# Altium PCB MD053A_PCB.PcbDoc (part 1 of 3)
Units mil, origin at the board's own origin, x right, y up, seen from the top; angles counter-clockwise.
Board outline 3650 x 5180 mil, 4 copper layers (Top Layer, GND Layer, Power Layer, Bottom Layer), stack 58.4 mil thick; 251 components, 138 nets, 532 pads, 1017 vias.
Unrouted connection lines stored in the file: 42.
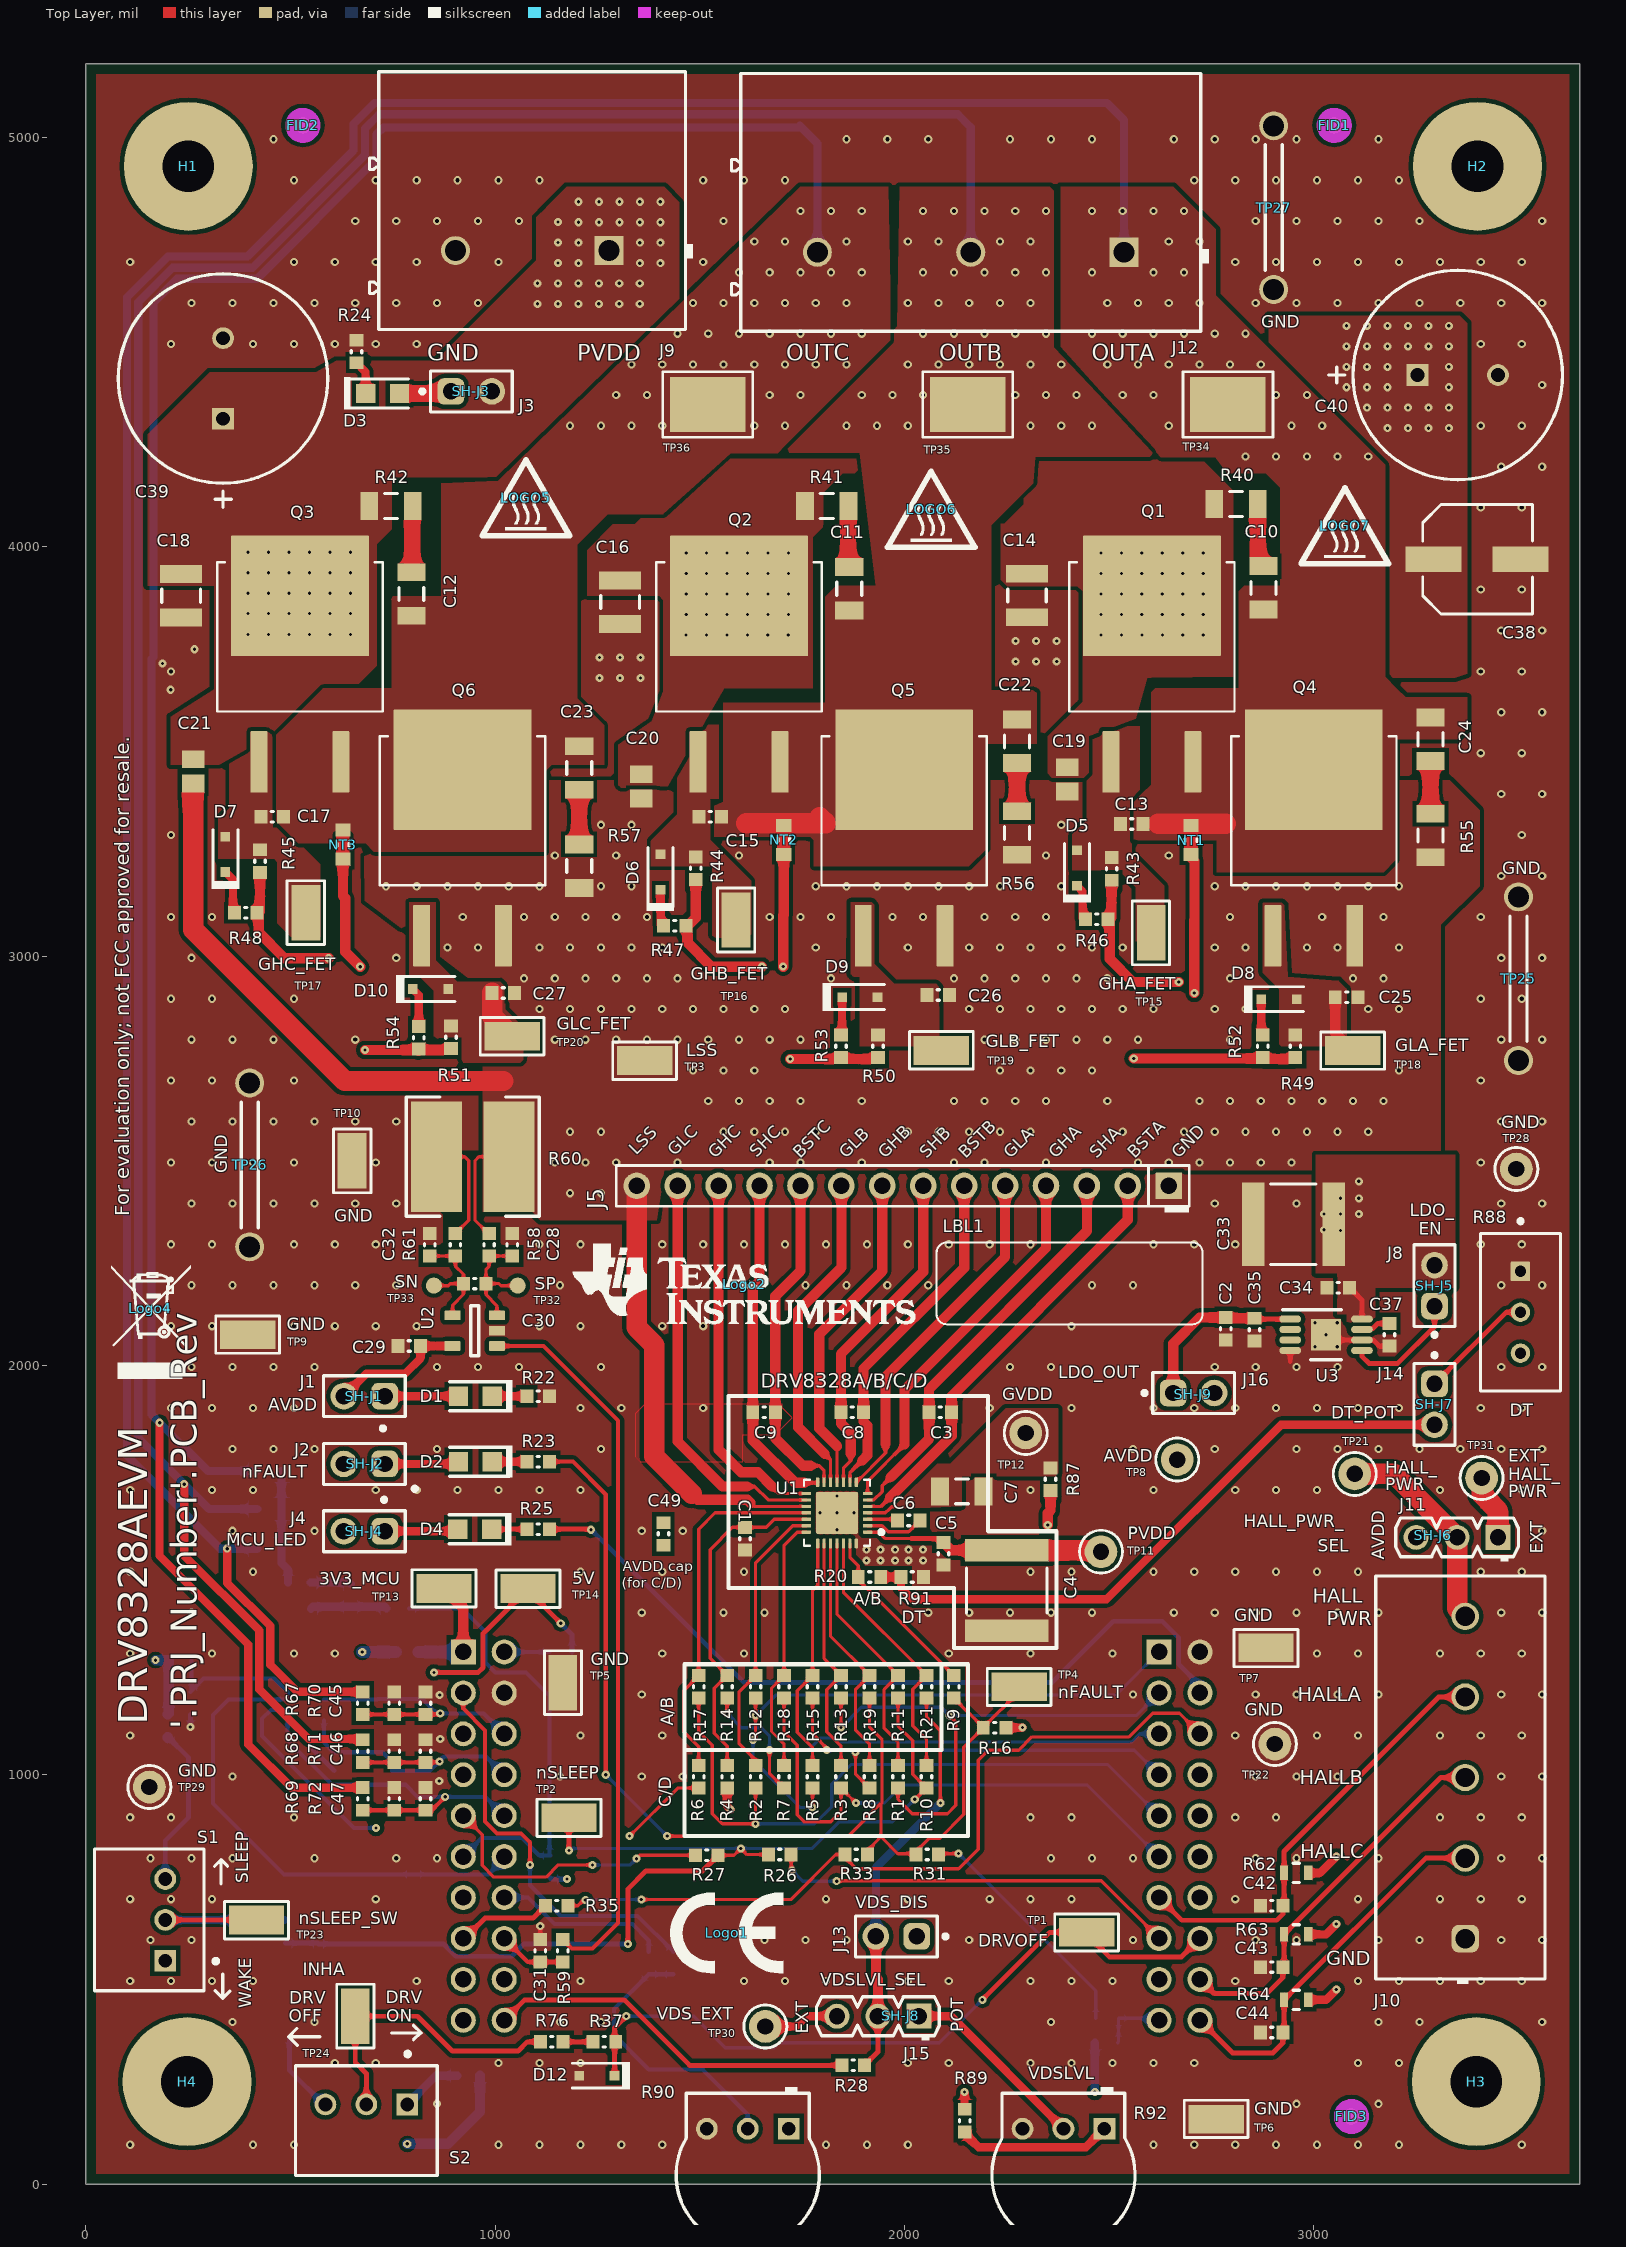
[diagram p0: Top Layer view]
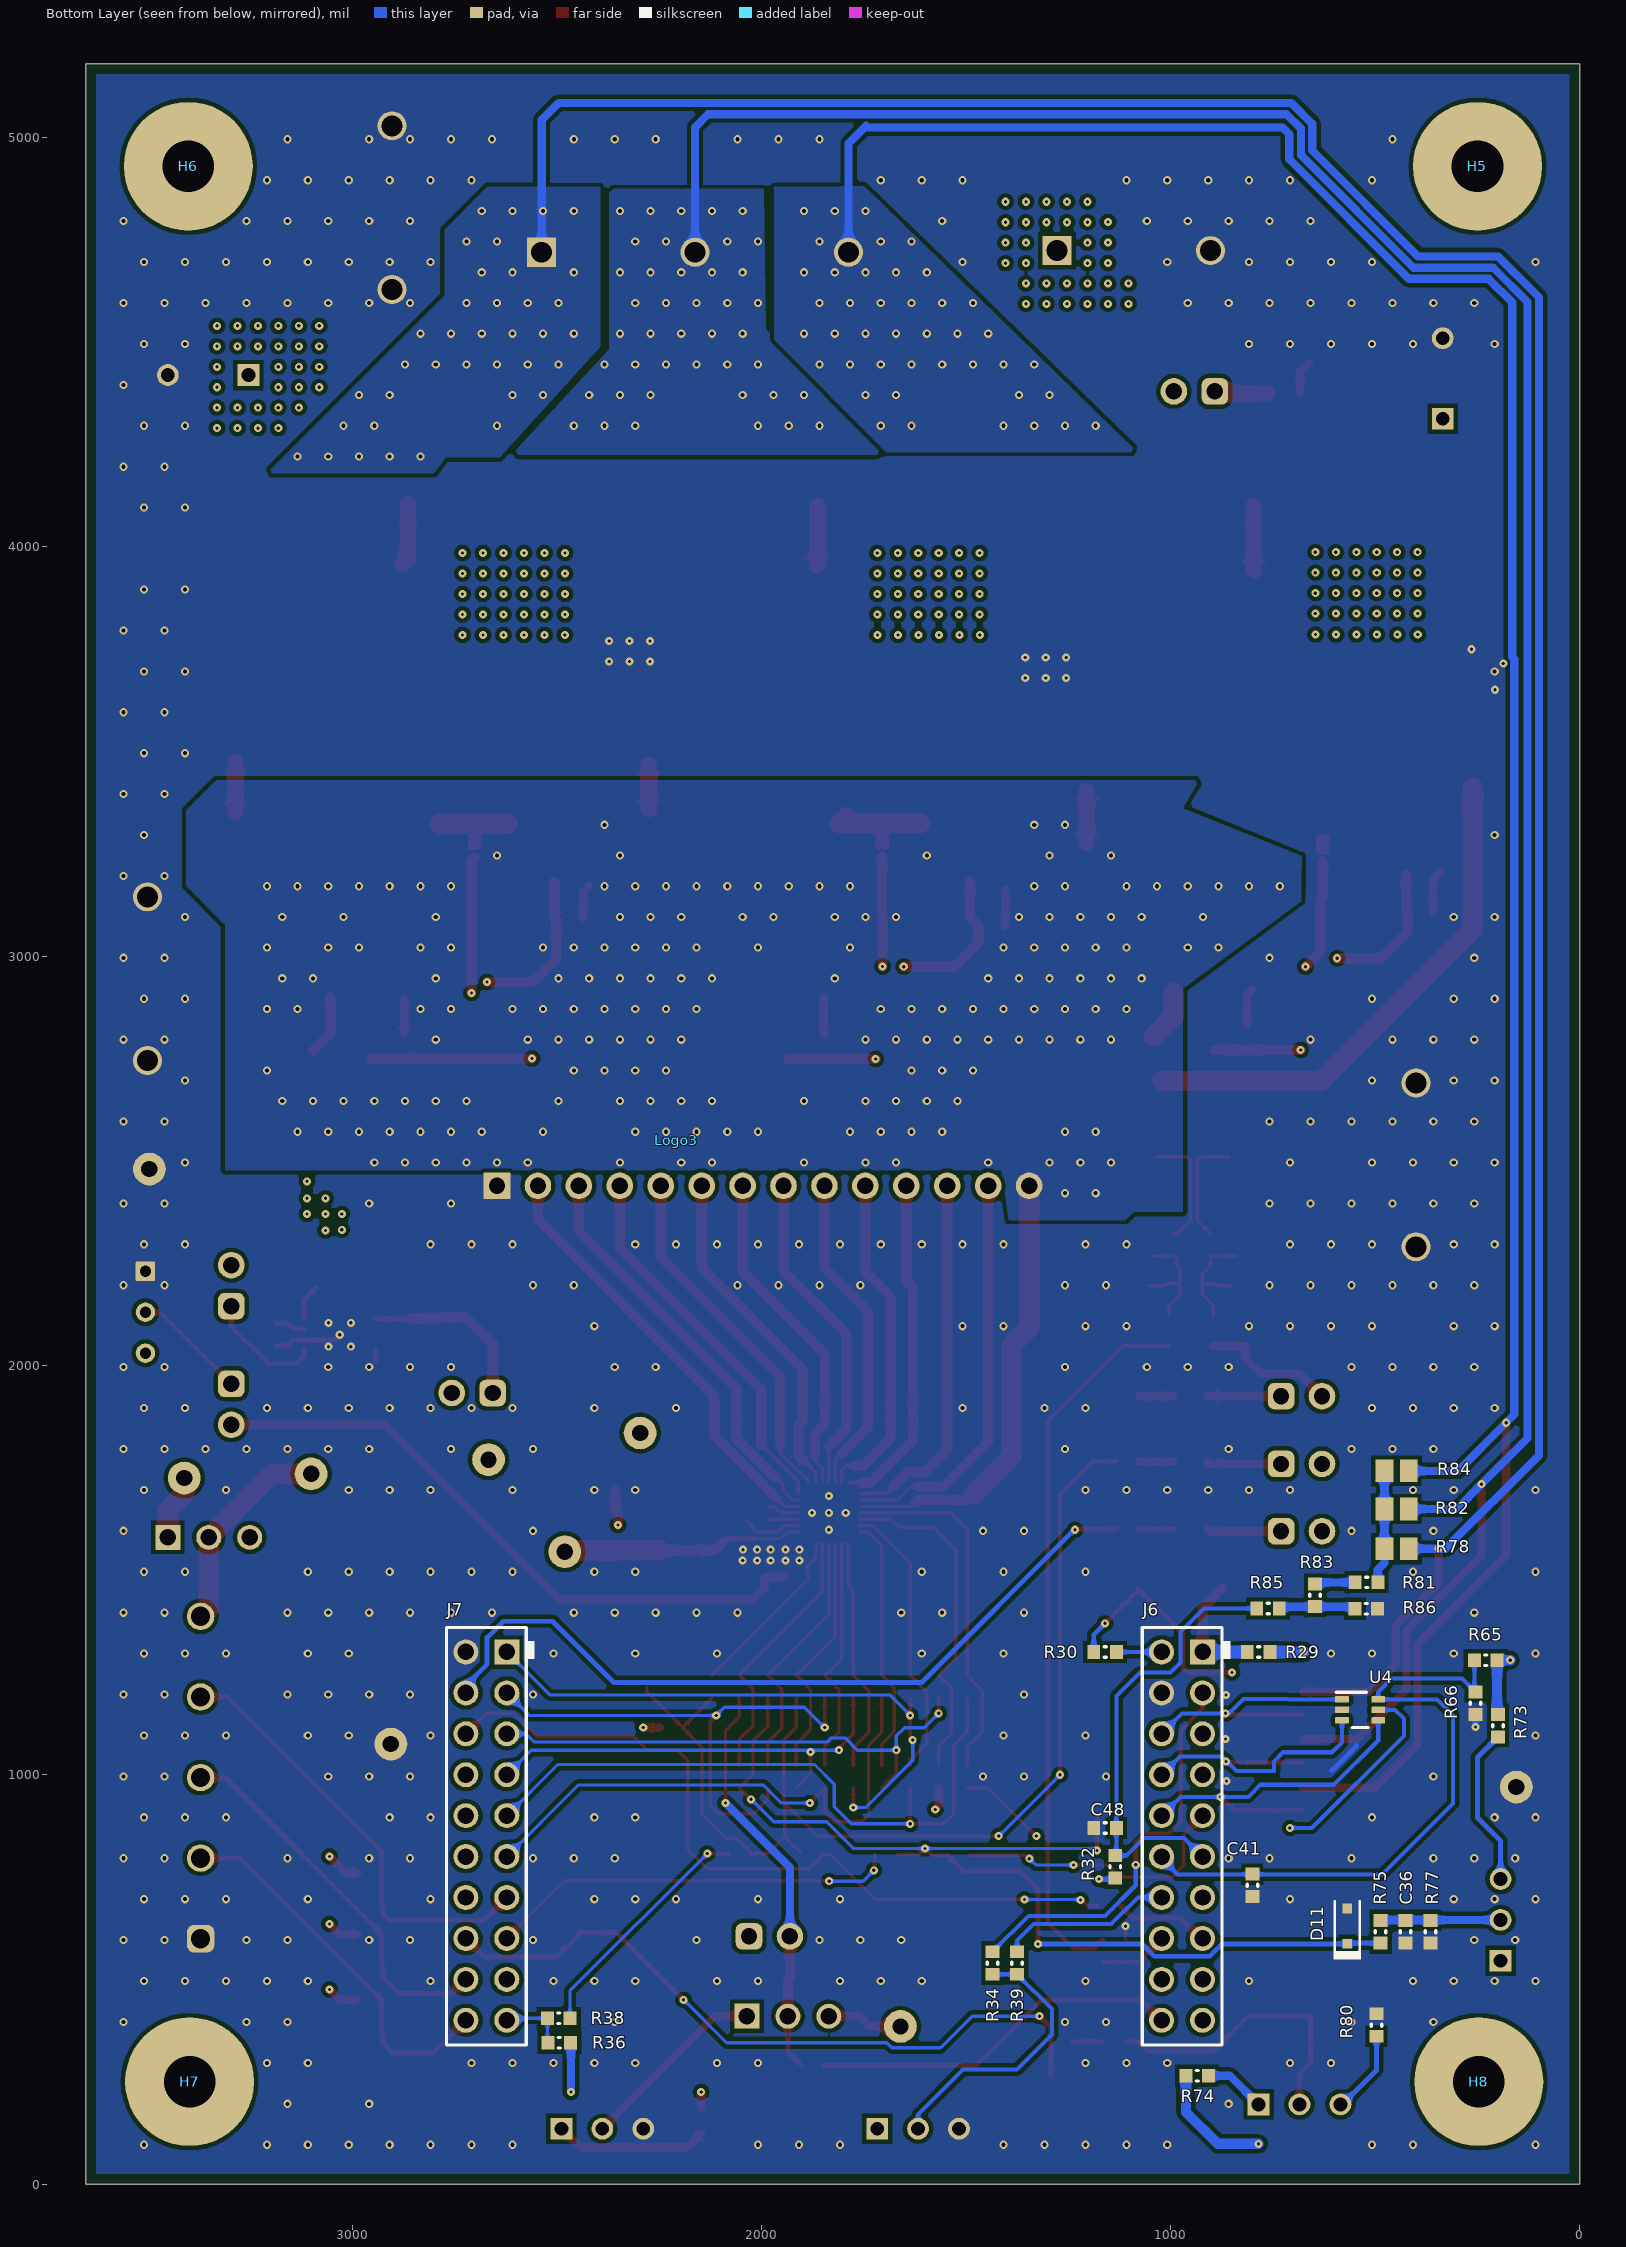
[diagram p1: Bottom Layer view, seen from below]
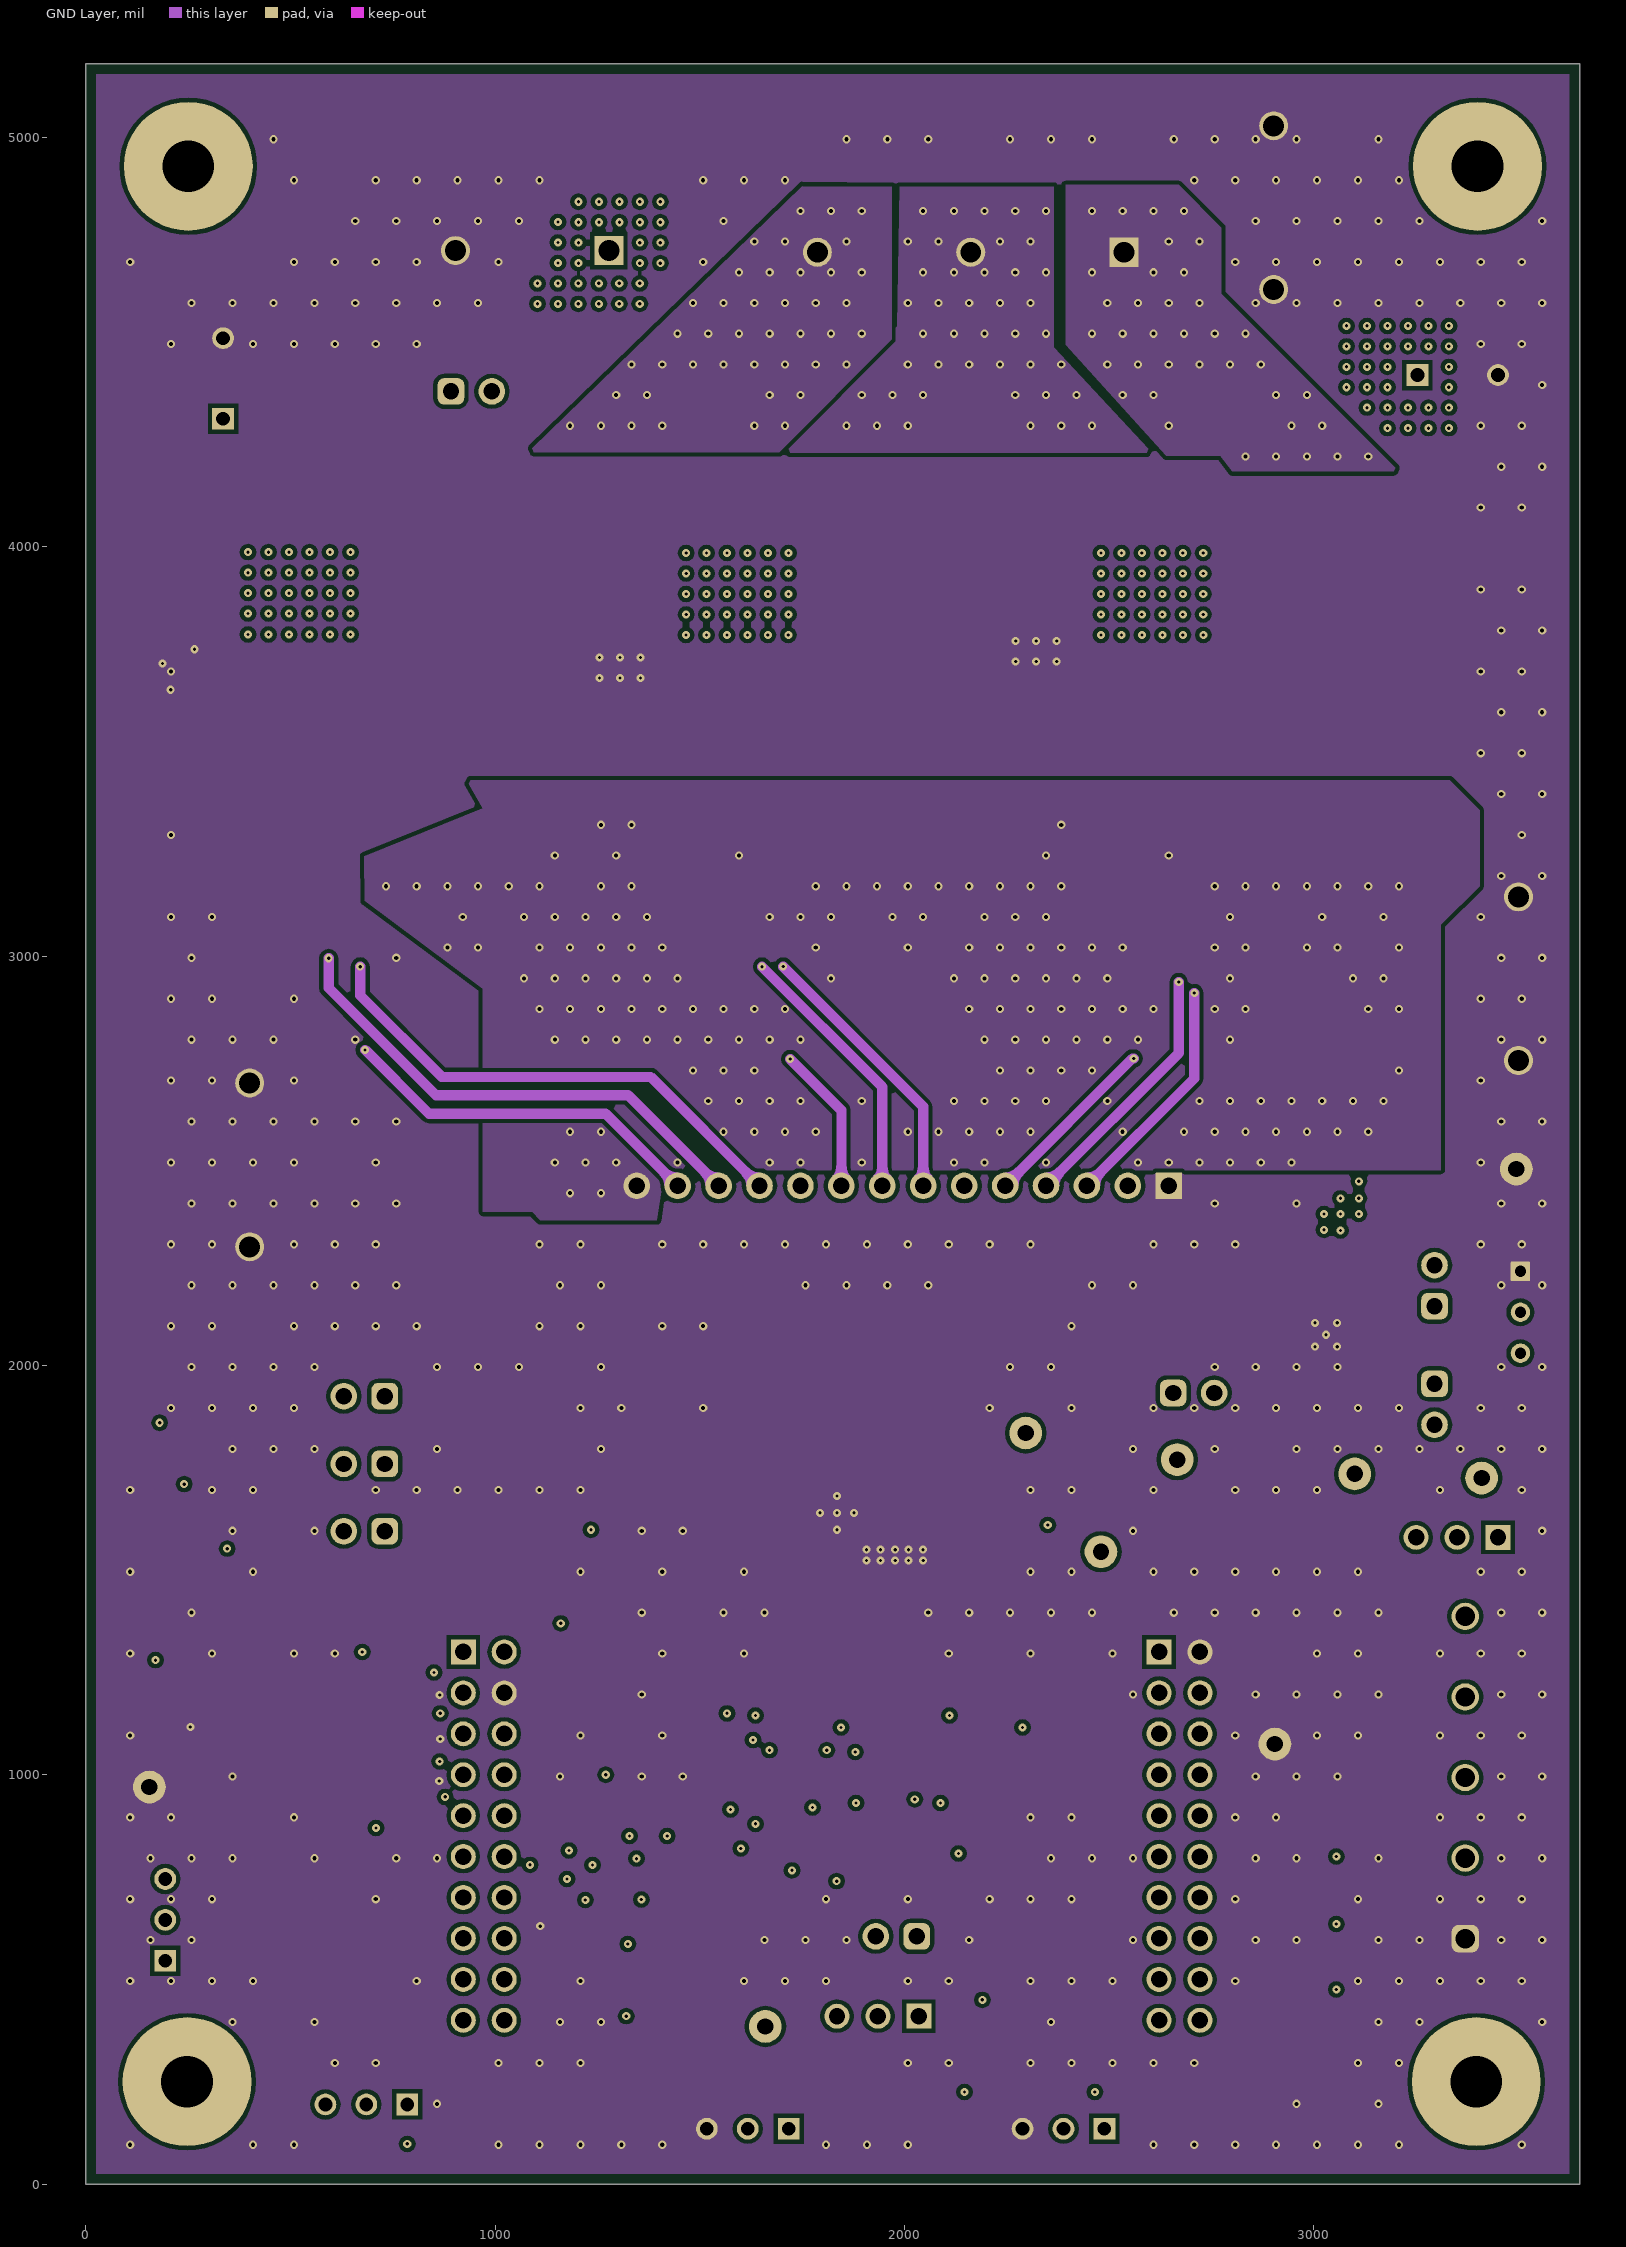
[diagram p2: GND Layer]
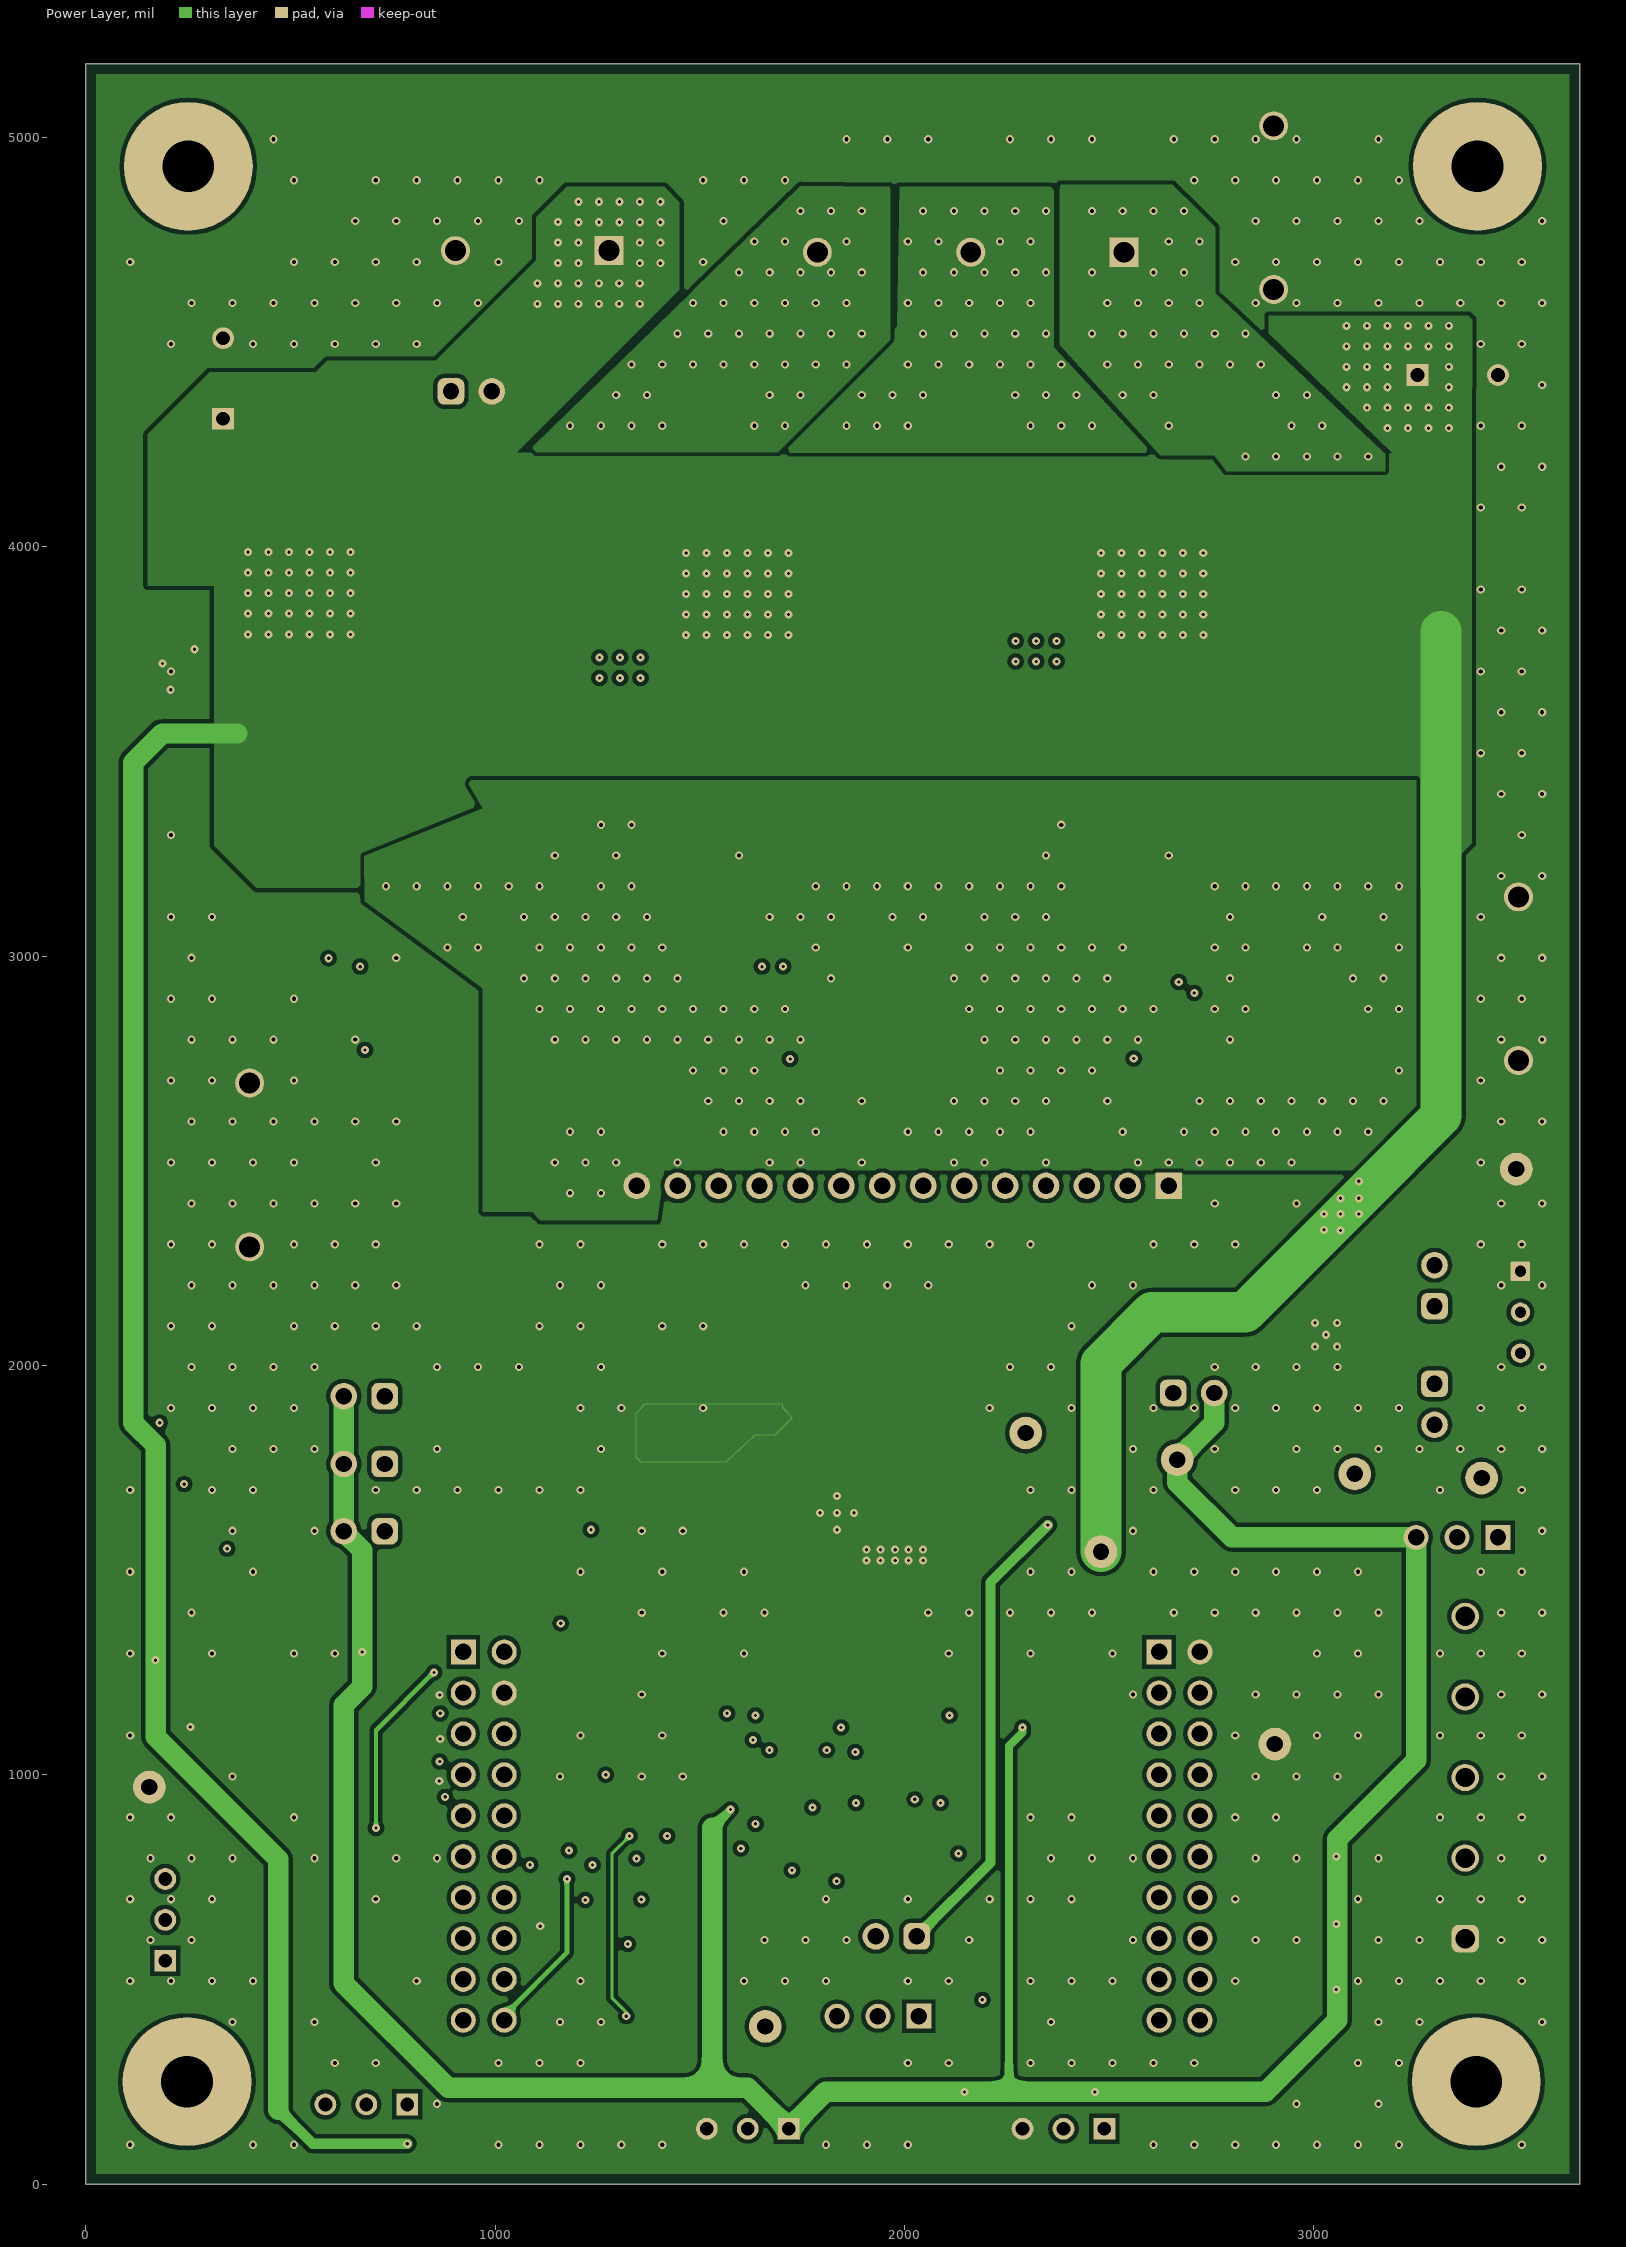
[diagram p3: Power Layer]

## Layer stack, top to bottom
Top Solder: solder mask 0.4, Solder Resist, Dk 3.5
Top Layer: signal copper 2.8
Dielectric 2: core 10, FR-4, Dk 4.8
GND Layer: signal copper 1.4
Dielectric 1: prepreg 30, FR-4, Dk 4.2
Power Layer: signal copper 1.4
Dielectric 3: core 10, FR-4, Dk 4.8
Bottom Layer: signal copper 2.8
Solder Side: solder mask 0.4, Solder Resist, Dk 3.5

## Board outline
0,0 3650,0 3650,5180 0,5180

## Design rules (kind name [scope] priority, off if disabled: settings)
AcuteAngle [All] p1: minimum=4.50000000000000E+0001 checktracksonly=FALSE
AssemblyTestPointUsage [All] p1: valid=2
BoardOutlineClearance BoardOutlineClearance_MountingHoles [OnCopper and InComponentClass('Mounting Holes')] p1: gap=39.37 ignorepadtopadclearanceinfootprint=FALSE
BoardOutlineClearance BoardOutlineClearance_Poly [OnCopper and IsPoly] p2: gap=25 ignorepadtopadclearanceinfootprint=FALSE
BoardOutlineClearance [OnCopper and Not InComponentClass('Logo') and not InComponentClass('FiducialMark') and not InRegion(1000,500,4000,800) and not InPoly] p3: gap=75 ignorepadtopadclearanceinfootprint=FALSE
Clearance Clearance_Keepouts [((IsTrack Or IsArc) And Not InPoly) And IsFree and IsKeepOut vs ((IsTrack Or IsArc) And Not InPoly) And IsFree and IsKeepOut] p1: gap=0 ignorepadtopadclearanceinfootprint=FALSE
Clearance Clearance_Poly [InPolygon] p2: gap=10 ignorepadtopadclearanceinfootprint=TRUE
Clearance Clearance_FiducialMark [IsKeepOut and InComponentClass('FiducialMark') vs IsPad and InComponentClass('FiducialMark')] p3: gap=0 ignorepadtopadclearanceinfootprint=FALSE
Clearance [All] p4: gap=7 ignorepadtopadclearanceinfootprint=TRUE
ComponentClearance ComponentClearance_MountingHoles_FiducialMarks [InComponentClass('Mounting Holes') vs InComponentClass('FiducialMark')] p1: gap=50 collisioncheckmode=3 verticalgap=10 showdistances=FALSE
ComponentClearance ComponentClearance_Shunt [InComponentClass('Header') vs InComponentClass('Shunt')] p2: gap=0 collisioncheckmode=3 verticalgap=0 showdistances=FALSE
ComponentClearance ComponentClearance_Logo [InComponentClass('Logo')] p3: gap=50 collisioncheckmode=3 verticalgap=10 showdistances=FALSE
ComponentClearance ComponentClearance_ScrewToNut [(HasFootprint('NY PMS 440 0025 PH')) vs (HasFootprint('Keystone_1902C'))] p4: gap=5 collisioncheckmode=3 verticalgap=10 showdistances=FALSE
ComponentClearance ComponentClearance_MountingHoles [InComponentClass('Mounting Holes')] p5: gap=10 collisioncheckmode=3 verticalgap=100000 showdistances=FALSE
ComponentClearance ComponentClearance_SmallPassives [HasFootprint('0201*') or HasFootprint('0402*') or HasFootprint('0508') or HasFootprint('0603*') or HasFootprint('0612') or HasFootprint('0805*') or HasFootprint('0815*') or HasFootprint('0830*') or HasFootprint('1206*') or HasFootprint('1210*') or HasFootprint('1808*') or HasFootprint('1812*') or HasFootprint('1825*') or HasFootprint('2010*') or HasFootprint('2220*') or HasFootprint('2225*') or HasFootprint('2512*') or HasFootprint('2728*') or HasFootprint('3518*') vs HasFootprint('0201*') or HasFootprint('0402*') or HasFootprint('0508') or HasFootprint('0603*') or HasFootprint('0612') or HasFootprint('0805*') or HasFootprint('0815*') or HasFootprint('0830*') or HasFootprint('1206*') or HasFootprint('1210*') or HasFootprint('1808*') or HasFootprint('1812*') or HasFootprint('1825*') or HasFootprint('2010*') or HasFootprint('2220*') or HasFootprint('2225*') or HasFootprint('2512*') or HasFootprint('2728*') or HasFootprint('3518*')] p6: gap=14.96 collisioncheckmode=3 verticalgap=10 showdistances=FALSE
ComponentClearance ComponentClearance_THtoSMT [IsThruComponent vs IsSMTComponent] p7: gap=40 collisioncheckmode=3 verticalgap=30 showdistances=FALSE
ComponentClearance ComponentClearance_THtoTH [IsThruComponent vs IsThruComponent] p8: gap=30 collisioncheckmode=3 verticalgap=30 showdistances=FALSE
ComponentClearance [All] p9: gap=30 collisioncheckmode=3 verticalgap=10 showdistances=FALSE
DiffPairsRouting [All] p1: maxlimit=100 minlimit=10 mostfreqgap=10 toplayer_minwidth=15 toplayer_maxwidth=15 toplayer_prefwidth=15 midlayer1_minwidth=15 midlayer1_maxwidth=15 midlayer1_prefwidth=15 midlayer2_minwidth=15 midlayer2_maxwidth=15 midlayer2_prefwidth=15 bottomlayer_minwidth=15 bottomlayer_maxwidth=15 bottomlayer_prefwidth=15 maxuncoupledlength=1000
FabricationTestPointUsage TestPointUsage [All] p1: valid=2 allowmultiple=FALSE
FabricationTestpoint Testpoint [All] p1: side=3 testpointundercomponent=TRUE minsize=40 maxsize=100 preferedsize=60 minholesize=0 maxholesize=40 preferedholesize=32 testpointgrid=1 allowsidetop=TRUE allowsidebottom=TRUE usegrid=TRUE gridtolerance=0.01
FanoutControl Fanout_LCC [IsLCC] p1: bgadir=Out bgaviamode=Centered fanoutstyle=Auto fanoutdirection=Alternating viagrid=1 // Fanout_LCC (Default Rule)
FanoutControl Fanout_BGA [IsBGA] p2: bgadir=Out bgaviamode=Centered fanoutstyle=Auto fanoutdirection=Alternating viagrid=1 // Fanout_BGA (Default Rule)
FanoutControl Fanout_Default [All] p4: bgadir=Out bgaviamode=Centered fanoutstyle=Auto fanoutdirection=Alternating viagrid=1 // Fanout_Default (Default Rule)
FanoutControl Fanout_Small [(CompPinCount < 5)] p5: bgadir=Out bgaviamode=Centered fanoutstyle=Auto fanoutdirection=OutThenIn viagrid=1 // Fanout_Small (Default Rule)
Height [All] p1 off: minheight=0 maxheight=1000 prefheight=500
HoleSize [All] p1: absolutevalues=TRUE maxlimit=251 minlimit=7.87 maxpercent=80.000 minpercent=20.000
MinimumAnnularRing MinimumAnnularRing_ThermalPadVias [IsVia and InAnyComponent] p1: minimumring=5.91
MinimumAnnularRing [All] p2: minimumring=5
MinimumSolderMaskSliver MinimumSolderMaskSliver_Logo [InComponentClass('Logo') vs InComponentClass('Logo')] p1: minsoldermaskwidth=0.7
MinimumSolderMaskSliver [All] p2: minsoldermaskwidth=1
PlaneConnect [All] p1: planeconnectstyle=Direct reliefexpansion=10 reliefentries=4 reliefconductorwidth=10 reliefairgap=10
PolygonConnect PolygonConnect_51 [All] p1: connectstyle=Direct reliefconductorwidth=10 reliefentries=4 polygonreliefangle="90 Angle" airgapwidth=10
PolygonConnect PolygonConnect_50 [All vs IsNamedPolygon('TOP_LAYER_PVDD_P078')] p2: connectstyle=Direct reliefconductorwidth=10 reliefentries=4 polygonreliefangle="90 Angle" airgapwidth=10
PolygonConnect PolygonConnect_49 [All vs IsNamedPolygon('TOP_LAYER_PVDD_P078')] p3: connectstyle=Direct reliefconductorwidth=10 reliefentries=4 polygonreliefangle="90 Angle" airgapwidth=10
PolygonConnect PolygonConnect_48 [All vs IsNamedPolygon('TOP_LAYER_PVDD_P078')] p4: connectstyle=Direct reliefconductorwidth=10 reliefentries=4 polygonreliefangle="90 Angle" airgapwidth=10
PolygonConnect PolygonConnect_47 [All vs IsNamedPolygon('TOP_LAYER_PVDD_P008')] p5: thpad.connectstyle=Direct thpad.reliefconductorwidth=10 thpad.reliefentries=4 thpad.polygonreliefangle="90 Angle" thpad.airgapwidth=10 smdpad.connectstyle=Direct smdpad.reliefconductorwidth=10 smdpad.reliefentries=4 smdpad.polygonreliefangle="90 Angle" smdpad.airgapwidth=10 via.connectstyle=Relief via.reliefconductorwidth=10 via.reliefentries=4 via.polygonreliefangle="90 Angle" via.airgapwidth=10
PolygonConnect PolygonConnect_46 [All vs IsNamedPolygon('BOTTOM_LAYER_GND_P080')] p6: connectstyle=Direct reliefconductorwidth=10 reliefentries=4 polygonreliefangle="90 Angle" airgapwidth=10
PolygonConnect PolygonConnect_45 [All vs IsNamedPolygon('BOTTOM_LAYER_OUTA_P076')] p7: connectstyle=Direct reliefconductorwidth=10 reliefentries=4 polygonreliefangle="90 Angle" airgapwidth=10
PolygonConnect PolygonConnect_44 [All vs IsNamedPolygon('BOTTOM_LAYER_OUTB_P074')] p8: connectstyle=Direct reliefconductorwidth=10 reliefentries=4 polygonreliefangle="90 Angle" airgapwidth=10
PolygonConnect PolygonConnect_43 [All vs IsNamedPolygon('BOTTOM_LAYER_OUTC_P072')] p9: connectstyle=Direct reliefconductorwidth=10 reliefentries=4 polygonreliefangle="90 Angle" airgapwidth=10
PolygonConnect PolygonConnect_42 [All vs IsNamedPolygon('BOTTOM_LAYER_NONET_P070')] p10: connectstyle=Direct reliefconductorwidth=10 reliefentries=4 polygonreliefangle="90 Angle" airgapwidth=10
PolygonConnect PolygonConnect_41 [All vs IsNamedPolygon('POWER_LAYER_GND_P078')] p11: connectstyle=Direct reliefconductorwidth=10 reliefentries=4 polygonreliefangle="90 Angle" airgapwidth=10
PolygonConnect PolygonConnect_40 [All vs IsNamedPolygon('GND_LAYER_GND_P074')] p12: connectstyle=Direct reliefconductorwidth=10 reliefentries=4 polygonreliefangle="90 Angle" airgapwidth=10
PolygonConnect PolygonConnect_39 [All vs IsNamedPolygon('TOP_LAYER_GND_P070')] p13: connectstyle=Direct reliefconductorwidth=10 reliefentries=4 polygonreliefangle="90 Angle" airgapwidth=10
PolygonConnect PolygonConnect_38 [All vs IsNamedPolygon('BOTTOM_LAYER_GND')] p14: connectstyle=Direct reliefconductorwidth=10 reliefentries=4 polygonreliefangle="90 Angle" airgapwidth=10
PolygonConnect PolygonConnect_37 [All vs IsNamedPolygon('BOTTOM_LAYER_GND')] p15: connectstyle=Direct reliefconductorwidth=10 reliefentries=4 polygonreliefangle="90 Angle" airgapwidth=10
PolygonConnect PolygonConnect_36 [All vs IsNamedPolygon('GND_LAYER_OUTA_P062')] p16: connectstyle=Direct reliefconductorwidth=10 reliefentries=4 polygonreliefangle="90 Angle" airgapwidth=10
PolygonConnect PolygonConnect_35 [All vs IsNamedPolygon('GND_LAYER_OUTB_P060')] p17: connectstyle=Direct reliefconductorwidth=10 reliefentries=4 polygonreliefangle="90 Angle" airgapwidth=10
PolygonConnect PolygonConnect_34 [All vs IsNamedPolygon('GND_LAYER_OUTC_P058')] p18: connectstyle=Direct reliefconductorwidth=10 reliefentries=4 polygonreliefangle="90 Angle" airgapwidth=10
PolygonConnect PolygonConnect_33 [All vs IsNamedPolygon('POWER_LAYER_PVDD_P056')] p19: connectstyle=Direct reliefconductorwidth=10 reliefentries=4 polygonreliefangle="90 Angle" airgapwidth=10
PolygonConnect PolygonConnect_32 [All vs IsNamedPolygon('POWER_LAYER_PVDD_P056')] p20: connectstyle=Direct reliefconductorwidth=10 reliefentries=4 polygonreliefangle="90 Angle" airgapwidth=10
PolygonConnect PolygonConnect_31 [All vs IsNamedPolygon('POWER_LAYER_OUTA_P052')] p21: connectstyle=Direct reliefconductorwidth=10 reliefentries=4 polygonreliefangle="90 Angle" airgapwidth=10
PolygonConnect PolygonConnect_30 [All vs IsNamedPolygon('POWER_LAYER_OUTB_P050')] p22: connectstyle=Direct reliefconductorwidth=10 reliefentries=4 polygonreliefangle="90 Angle" airgapwidth=10
PolygonConnect PolygonConnect_29 [All vs IsNamedPolygon('POWER_LAYER_OUTC_P048')] p23: connectstyle=Direct reliefconductorwidth=10 reliefentries=4 polygonreliefangle="90 Angle" airgapwidth=10
PolygonConnect PolygonConnect_28 [All vs IsNamedPolygon('POWER_LAYER_AVDD_P064')] p24: connectstyle=Direct reliefconductorwidth=10 reliefentries=4 polygonreliefangle="90 Angle" airgapwidth=10
PolygonConnect PolygonConnect_27 [All vs IsNamedPolygon('SIGNAL_LAYER_1_OUTA_P060')] p25: connectstyle=Direct reliefconductorwidth=10 reliefentries=4 polygonreliefangle="90 Angle" airgapwidth=10
PolygonConnect PolygonConnect_26 [All vs IsNamedPolygon('SIGNAL_LAYER_1_OUTB_P058')] p26: connectstyle=Direct reliefconductorwidth=10 reliefentries=4 polygonreliefangle="90 Angle" airgapwidth=10
PolygonConnect PolygonConnect_25 [All vs IsNamedPolygon('SIGNAL_LAYER_1_OUTC_P056')] p27: connectstyle=Direct reliefconductorwidth=10 reliefentries=4 polygonreliefangle="90 Angle" airgapwidth=10
PolygonConnect PolygonConnect_24 [All vs IsNamedPolygon('SIGNAL_LAYER_2_PVDD_P054')] p28: connectstyle=Direct reliefconductorwidth=10 reliefentries=4 polygonreliefangle="90 Angle" airgapwidth=10
PolygonConnect PolygonConnect_23 [All vs IsNamedPolygon('SIGNAL_LAYER_2_PVDD_P052')] p29: connectstyle=Direct reliefconductorwidth=10 reliefentries=4 polygonreliefangle="90 Angle" airgapwidth=10
PolygonConnect PolygonConnect_22 [All vs IsNamedPolygon('SIGNAL_LAYER_2_OUTA_P050')] p30: connectstyle=Direct reliefconductorwidth=10 reliefentries=4 polygonreliefangle="90 Angle" airgapwidth=10
PolygonConnect PolygonConnect_21 [All vs IsNamedPolygon('SIGNAL_LAYER_2_OUTB_P048')] p31: connectstyle=Direct reliefconductorwidth=10 reliefentries=4 polygonreliefangle="90 Angle" airgapwidth=10
PolygonConnect PolygonConnect_20 [All vs IsNamedPolygon('SIGNAL_LAYER_2_OUTC_P046')] p32: connectstyle=Direct reliefconductorwidth=10 reliefentries=4 polygonreliefangle="90 Angle" airgapwidth=10
PolygonConnect PolygonConnect_19 [All vs IsNamedPolygon('TOP_LAYER_AVDD_P046')] p33: connectstyle=Direct reliefconductorwidth=10 reliefentries=4 polygonreliefangle="90 Angle" airgapwidth=10
PolygonConnect PolygonConnect_18 [All vs IsNamedPolygon('TOP_LAYER_PVDD_P034')] p34: connectstyle=Direct reliefconductorwidth=10 reliefentries=4 polygonreliefangle="90 Angle" airgapwidth=10
PolygonConnect PolygonConnect_17 [All vs IsNamedPolygon('SIGNAL_LAYER_1_OUTC_P036')] p35: connectstyle=Direct reliefconductorwidth=10 reliefentries=4 polygonreliefangle="90 Angle" airgapwidth=10
PolygonConnect PolygonConnect_16 [All vs IsNamedPolygon('TOP_LAYER_PVDD_P034')] p36: connectstyle=Direct reliefconductorwidth=10 reliefentries=4 polygonreliefangle="90 Angle" airgapwidth=10
PolygonConnect PolygonConnect_15 [All vs IsNamedPolygon('TOP_LAYER_LSS_P030')] p37: connectstyle=Direct reliefconductorwidth=10 reliefentries=4 polygonreliefangle="90 Angle" airgapwidth=10
PolygonConnect PolygonConnect_14 [All vs IsNamedPolygon('TOP_LAYER_GLC_FET_P024')] p38: connectstyle=Direct reliefconductorwidth=10 reliefentries=4 polygonreliefangle="90 Angle" airgapwidth=10
PolygonConnect PolygonConnect_13 [All vs IsNamedPolygon('TOP_LAYER_GLB_FET_P026')] p39: connectstyle=Direct reliefconductorwidth=10 reliefentries=4 polygonreliefangle="90 Angle" airgapwidth=10
PolygonConnect PolygonConnect_12 [All vs IsNamedPolygon('TOP_LAYER_GLA_FET_P028')] p40: connectstyle=Direct reliefconductorwidth=10 reliefentries=4 polygonreliefangle="90 Angle" airgapwidth=10
PolygonConnect PolygonConnect_11 [All vs IsNamedPolygon('TOP_LAYER_GHB_FET_P020')] p41: connectstyle=Direct reliefconductorwidth=10 reliefentries=4 polygonreliefangle="90 Angle" airgapwidth=10
PolygonConnect PolygonConnect_10 [All vs IsNamedPolygon('TOP_LAYER_GHA_FET_P022')] p42: connectstyle=Direct reliefconductorwidth=10 reliefentries=4 polygonreliefangle="90 Angle" airgapwidth=10
PolygonConnect PolygonConnect_9 [All vs IsNamedPolygon('TOP_LAYER_GHC_FET_P018')] p43: connectstyle=Direct reliefconductorwidth=10 reliefentries=4 polygonreliefangle="90 Angle" airgapwidth=10
PolygonConnect PolygonConnect_8 [All vs IsNamedPolygon('TOP_LAYER_GND_P014')] p44: connectstyle=Direct reliefconductorwidth=10 reliefentries=4 polygonreliefangle="90 Angle" airgapwidth=10
PolygonConnect PolygonConnect_7 [All vs IsNamedPolygon('TOP_LAYER_GND_P014')] p45: connectstyle=Direct reliefconductorwidth=10 reliefentries=4 polygonreliefangle="90 Angle" airgapwidth=10
PolygonConnect PolygonConnect_6 [All vs IsNamedPolygon('TOP_LAYER_PVDD_P008')] p46: connectstyle=Direct reliefconductorwidth=10 reliefentries=4 polygonreliefangle="90 Angle" airgapwidth=10
PolygonConnect PolygonConnect_5 [All vs IsNamedPolygon('TOP_LAYER_PVDD_P008')] p47: connectstyle=Direct reliefconductorwidth=10 reliefentries=4 polygonreliefangle="90 Angle" airgapwidth=10
PolygonConnect PolygonConnect_4 [All vs IsNamedPolygon('TOP_LAYER_PVDD_P008')] p48: connectstyle=Direct reliefconductorwidth=10 reliefentries=4 polygonreliefangle="90 Angle" airgapwidth=10
PolygonConnect PolygonConnect_3 [All vs IsNamedPolygon('TOP_LAYER_OUTA_P006')] p49: connectstyle=Direct reliefconductorwidth=10 reliefentries=4 polygonreliefangle="90 Angle" airgapwidth=10
PolygonConnect PolygonConnect_2 [All vs IsNamedPolygon('TOP_LAYER_OUTB_P004')] p50: connectstyle=Direct reliefconductorwidth=10 reliefentries=4 polygonreliefangle="90 Angle" airgapwidth=10
PolygonConnect PolygonConnect_1 [All vs IsNamedPolygon('TOP_LAYER_OUTC_P002')] p51: connectstyle=Direct reliefconductorwidth=10 reliefentries=4 polygonreliefangle="90 Angle" airgapwidth=10
PolygonConnect [All] p52: connectstyle=Relief reliefconductorwidth=10 reliefentries=4 polygonreliefangle="90 Angle" airgapwidth=10
RoutingVias ThermalPadVias [IsVia and InAnyComponent] p1: holewidth=7.87 width=19.68 viastyle="Through Hole" minholewidth=7.87 minwidth=19.68 maxholewidth=12.99 maxwidth=23.62
RoutingVias [All] p2: holewidth=7.87 width=19.68 viastyle="Through Hole" minholewidth=7.87 minwidth=19.68 maxholewidth=10 maxwidth=20
SilkToBoardRegionClearance [Not ((IsComment or IsDesignator) And (Hide <> 'False')) and not InRegion(1000,500,4000,800)] p1:
SilkToSilkClearance SilkToSilkClearance_Pb-FreeLogo [(HasFootprint('Pb-Free_Overlay_Medium') OR HasFootprint('Pb-Free_Overlay_Small')) vs (HasFootprint('Pb-Free_Overlay_Medium') OR HasFootprint('Pb-Free_Overlay_Small'))] p1: silktosilkclearance=0
SilkToSilkClearance [All] p2: silktosilkclearance=0
SilkToSolderMaskClearance SilkToComponentPadClearance [(IsPad or IsFill or IsRegion) and InAnycomponent] p1: minsilkscreentomaskgap=0 clearancetoexposedcopper=TRUE
SilkToSolderMaskClearance "Silk to Solder Mask Opening" [All] p2: minsilkscreentomaskgap=0 clearancetoexposedcopper=FALSE
SolderMaskExpansion [All] p1: expansion=1.97
UnRoutedNet [All] p1: checkbadconnections=TRUE
Width [All] p1: maxlimit=100 minlimit=6 preferedwidth=10 checkconnectedcopper=TRUE
13 further rules are at their usual default settings.

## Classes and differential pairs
component class MD053A_LDO: C2 C33 C34 C35 C37 J8 J16 SH-J5 SH-J9 U3
component class Label: LBL1
component class Shunt: SH-J1 SH-J2 SH-J3 SH-J4 SH-J5 SH-J6 SH-J7 SH-J8 SH-J9
component class MD053A_POWER_AND_CONNECTORS: C36 C38 C39 C40 C41 C42 C43 C44 C45 C46 C47 C48 D11 D12 GND1 GND2 GND3 J9 J10 J11 J12 J13 J14 J15 R37 R62 R63 R64 R65 R66 R67 R68 R69 R70 R71 R72 R73 R74 R75 R76 R77 R78 R80 R81 R82 R83 R84 R85 R86 R87 R88 R89 R90 R91 R92 S1 S2 SH-J6 SH-J7 SH-J8 TP21 TP22 TP23 TP24 TP25 TP26 TP27 TP28 TP29 TP30 TP31 TP34 TP35 TP36 TP37 TP38 U4
component class MD053A_FETS_AND_POWER_STAGE: C10 C11 C12 C13 C14 C15 C16 C17 C18 C19 C20 C21 C22 C23 C24 C25 C26 C27 C28 C29 C30 C31 C32 D5 D6 D7 D8 D9 D10 NT1 NT2 NT3 Q1 Q2 Q3 Q4 Q5 Q6 R40 R41 R42 R43 R44 R45 R46 R47 R48 R49 R50 R51 R52 R53 R54 R55 R56 R57 R58 R59 R60 R61 TP15 TP16 TP17 TP18 TP19 TP20 TP32 TP33 U2
component class MD053A_DRIVER: C1 C3 C4 C5 C6 C7 C8 C9 C49 D1 D2 D3 D4 J1 J2 J3 J4 J5 J6 J7 R1 R2 R3 R4 R5 R6 R7 R8 R9 R10 R11 R12 R13 R14 R15 R16 R17 R18 R19 R20 R21 R22 R23 R24 R25 R26 R27 R28 R29 R30 R31 R32 R33 R34 R35 R36 R38 R39 SH-J1 SH-J2 SH-J3 SH-J4 TP1 TP2 TP3 TP4 TP5 TP6 TP7 TP8 TP9 TP10 TP11 TP12 TP13 TP14 U1
component class Header: J1 J2 J3 J4 J5 J8 J11 J13 J14 J15 J16
component class "Mounting Holes": H1 H2 H3 H4
component class Logo: Logo2
component class MD053A_Hardware: FID1 FID2 FID3 H1 H2 H3 H4 H5 H6 H7 H8 LBL1 Logo1 Logo2 Logo3 Logo4 LOGO5 LOGO6 LOGO7 ZZ1 ZZ2 ZZ3 ZZ4
component class FiducialMark: FID1 FID2 FID3
component class AssemblyNote: ZZ1 ZZ2 ZZ3 ZZ4

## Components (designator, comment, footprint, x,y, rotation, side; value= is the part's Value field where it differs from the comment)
C1 "C0603C105K9RACAUTO" 0603L 1610,1577.01 r90 top value=1uF
C2 "C0603C104K9PAC7867" 0603L 2785,2089.76 r270 top value=0.1uF
C3 "C1608X5R1H105K080AB" 0603L 2087.56,1885.43 r180 top value=1uF
C4 "22201C106MAT2A" 2220_280L 2250,1450 r270 top value=10uF
C5 "GRM188R72A104KA35J" 0603L 2095,1540 r270 top value=0.1uF
C6 "GRM188R71E474KA12D" 0603L 2010,1621.31 r0 top value=0.47uF
C7 "UMK316BBJ106KL-T" 1206_190L 2140,1692.43 r0 top value=10uF
C8 "C1608X5R1H105K080AB" 0603L 1872.16,1885.43 r180 top value=1uF
C9 "C1608X5R1H105K080AB" 0603L 1656.76,1885.43 r180 top value=1uF
C10 "12061C392KAZ2A" 1206L 2877.09,3900 r90 top value=3900pF
C11 "12061C392KAZ2A" 1206L 1865,3897.91 r90 top value=3900pF
C12 "12061C392KAZ2A" 1206L 795,3885 r90 top value=3900pF
C13 "GRM188R71H202KA01D" 0603L 2555.16,3323.01 r0 top value=2000pF
C14 "C1210C225K1RACTU" 1210_210L 2299.25,3881.34 r270 top value=2.2uF
C15 "GRM188R71H202KA01D" 0603L 1525,3340.67 r0 top value=2000pF
C16 "C1210C225K1RACTU" 1210_210L 1305,3865 r270 top value=2.2uF
C17 "GRM188R71H202KA01D" 0603L 454.93,3340.67 r0 top value=2000pF
C18 "C1210C225K1RACTU" 1210_210L 232.32,3880.75 r270 top value=2.2uF
C19 "08051C103JAT2A" 0805L 2397.68,3431.97 r270 top value=0.01uF
C20 "08051C103JAT2A" 0805L 1356.8,3415 r270 top value=0.01uF
C21 "08051C103JAT2A" 0805L 261.85,3451.65 r270 top value=0.01uF
C22 "12061C392KAZ2A" 1206L 2275,3525 r270 top value=3900pF
C23 "12061C392KAZ2A" 1206L 1205,3460 r270 top value=3900pF
C24 "12061C392KAZ2A" 1206L 3285,3530 r270 top value=3900pF
C25 "GRM188R71H202KA01D" 0603L 3080,2900 r0 top value=2000pF
C26 "GRM188R71H202KA01D" 0603L 2082.32,2905 r0 top value=2000pF
C27 "GRM188R71H202KA01D" 0603L 1019.72,2910.32 r0 top value=2000pF
C28 "06031C331KAT2A" 0603L 1041.38,2295 r270 top value=330pF
C29 "C0603C104J4RACTU" 0603L 790,2047.6 r180 top value=0.1uF
C30 "C1608NP01H103J080AA" 0603L 950,2200 r180 top value=0.01uF
C31 "GRM188R71C222KA01D" 0603L 1110,570 r90 top value=2200pF
C32 "06031C331KAT2A" 0603L 840,2295 r90 top value=330pF
C33 "22201C106MAT2A" 2220_280L 2950,2345 r180 top value=10uF
C34 "GRM188R72A104KA35J" 0603L 3060,2190 r180 top value=0.1uF
C35 "C0603C106M9PACTU" 0603L 2855,2087.8 r270 top value=10uF
C36 "GRM188R72A222KA01D" 0603L 425.93,616.22 r270 bottom value=2200pF
C37 "GRM188R71H202KA01D" 0603L 3185,2075 r270 top value=2000pF
C38 "EMZA800ADA100MF80G" CAPSMT_62_F80 3398.7,3970 r0 top value=10uF
C39 "EKYB101ELL391MK35S" KYB_1250x3500 335,4411.57 r90 top value=390uF
C40 "EKYB101ELL391MK35S" KYB_1250x3500 3351.57,4420 r0 top value=390uF
C41 "06035C104JAT2A" 0603L 800,730 r270 bottom value=0.1uF
C42 "885012206034" 0603L 2896.85,680 r180 top value=1000pF
C43 "885012206034" 0603L 2896.85,530 r180 top value=1000pF
C44 "885012206034" 0603L 2896.85,370 r180 top value=1000pF
C45 "06035C104JAT2A" 0603L 829.77,1175 r270 top value=0.1uF
C46 "06035C104JAT2A" 0603L 829.77,1057.93 r90 top value=0.1uF
C47 "06035C104JAT2A" 0603L 829.77,940.86 r90 top value=0.1uF
C48 "0603ZC100KAT2A" 0603L 1160,870 r0 bottom value=10pF
C49 "C0603C105K9RACAUTO" 0603L 1410.85,1588.28 r90 top value=1uF
D1 "LTST-C170KGKT" LTST-C170KGKT_Green 951.34,1925 r0 top value=Green
D2 "LTST-C170KRKT" LED_LTST-C170_Red 951.34,1765 r0 top value=Red
D3 "LTST-C170KGKT" LTST-C170KGKT_Green 724.65,4375 r180 top value=Green
D4 "LTST-C170KFKT" LTST-C170KFKT_Orange 950,1600 r0 top value=Orange
D5 "1N4448WX-TP" SOD-323 2421.3,3215.43 r90 top value=75V
D6 "1N4448WX-TP" SOD-323 1403.58,3205.59 r90 top value=75V
D7 "1N4448WX-TP" SOD-323 340.59,3248.9 r90 top value=75V
D8 "1N4448WX-TP" SOD-323 2915,2895 r0 top value=75V
D9 "1N4448WX-TP" SOD-323 1890.8,2900 r0 top value=75V
D10 "1N4448WX-TP" SOD-323 841.57,2919.83 r0 top value=75V
D11 "SZMM3Z3V3ST1G" SOD-323 568.19,630 r90 bottom value=3.3V
D12 "SZMM3Z3V3ST1G" SOD-323 1248.22,264.71 r180 top value=3.3V
FID1 "Fiducial" Fiducial10-20 3050,5030 r0 top
FID2 "Fiducial" Fiducial10-20 530,5030 r0 top
FID3 "Fiducial" Fiducial10-20 3091.85,165 r0 top
H1 "NY PMS 440 0025 PH" "NY PMS 440 0025 PH" 250,4930 r0 top
H2 "NY PMS 440 0025 PH" "NY PMS 440 0025 PH" 3400,4930 r0 top
H3 "NY PMS 440 0025 PH" "NY PMS 440 0025 PH" 3396.85,250 r0 top
H4 "NY PMS 440 0025 PH" "NY PMS 440 0025 PH" 246.85,250 r0 top
H5 "1902C" Keystone_1902C 250.36,4930 r180 bottom
H6 "1902C" Keystone_1902C 3400.36,4930 r180 bottom
H7 "1902C" Keystone_1902C 3396.85,250 r180 bottom
H8 "1902C" Keystone_1902C 246.85,250 r180 bottom
J1 "TSW-102-07-G-S" TSW-102-07-G-S 680,1925 r180 top
J2 "TSW-102-07-G-S" TSW-102-07-G-S 680,1759.41 r180 top
J3 "TSW-102-07-G-S" TSW-102-07-G-S 941.77,4380 r0 top
J4 "TSW-102-07-G-S" TSW-102-07-G-S 680,1595 r180 top
J5 "TSW-114-07-G-S" TSW-114-07-G-S 1995.67,2438.91 r180 top
J6 "SSQ-110-03-G-D" Samtec_SSQ-110-03-x-D 971.85,850 r270 bottom
J7 "SSQ-110-03-G-D" Samtec_SSQ-110-03-x-D 2671.85,850 r270 bottom
J8 "LDO_EN" TSW-102-07-G-S 3295,2195 r90 top
J9 "PVDD_IN" Phoenix_1902547 1090,4846 r180 top
J10 "HALL IN" Phoenix_1792892 3370,993.15 r90 top
J11 "HALL_PWR_SEL" FCI_68001-403HLF 3350,1580 r180 top
J12 "MOTOR_OUT" Phoenix_1904150 2161.8,4842.05 r180 top
J13 "VDS_DISABLE" TSW-102-07-G-S 1980,605 r180 top
J14 "TSW-102-07-G-S" TSW-102-07-G-S 3295,1905 r270 top
J15 "VDSLVL_SEL" FCI_68001-403HLF 1935,410 r180 top
J16 "LDO_OUT" TSW-102-07-G-S 2706.37,1932.76 r0 top
LBL1 "THT-14-423-10" Label_650x200 2403.39,2200.6 r0 top
Logo1 "CE Mark" CE_Mark_5mm 1565.65,613.45 r0 top
Logo2 "Texas Instruments" TI_Stacked_Overlay_Small 1608.01,2198.78 r0 top
Logo3 "FCC disclaimer" FCC_disclaimer 2208,2550 r180 bottom
Logo4 "WEEE logo" WEEE_Minimum 156.74,2140 r0 top
LOGO5 "CAUTION HOT SURFACE" IEC_HotSurface_Small 1075,4120 r0 top
LOGO6 "CAUTION HOT SURFACE" IEC_HotSurface_Small 2065,4092 r0 top
LOGO7 "CAUTION HOT SURFACE" IEC_HotSurface_Small 3076.02,4052 r0 top
NT1 "Net-Tie" NetTie_0603 2700,3283.5 r90 top net-tie
NT2 "Net-Tie" NetTie_0603 1704.76,3284.33 r90 top net-tie
NT3 "Net-Tie" NetTie_0603 627.77,3272.52 r90 top net-tie
Q1 "CSD18536KTTT" KTT0002A-MFG 2604.37,3780 r0 top
Q2 "CSD18536KTTT" KTT0002A-MFG 1595.51,3780 r0 top
Q3 "CSD18536KTTT" KTT0002A-MFG 522.68,3780 r0 top
Q4 "CSD18536KTTT" KTT0002A-MFG 3000,3355 r0 top
Q5 "CSD18536KTTT" KTT0002A-MFG 1999.05,3355 r0 top
Q6 "CSD18536KTTT" KTT0002A-MFG 920,3355.31 r0 top
R1 "ERJ-3GEY0R00V" 0603L 1984.06,995 r90 top value=0
R2 "ERJ-3GEY0R00V" 0603L 1636.11,995 r90 top value=0
R3 "ERJ-3GEY0R00V" 0603L 1844.88,995 r90 top value=0
R4 "ERJ-3GEY0R00V" 0603L 1566.52,995 r90 top value=0
R5 "ERJ-3GEY0R00V" 0603L 1775.29,995 r90 top value=0
R6 "ERJ-3GEY0R00V" 0603L 1496.93,995 r90 top value=0
R7 "ERJ-3GEY0R00V" 0603L 1705.7,995 r90 top value=0
R8 "ERJ-3GEY0R00V" 0603L 1914.47,995 r90 top value=0
R9 "ERJ-3GEY0R00V" 0603L 2120.5,1215 r90 top value=0
R10 "ERJ-3GEY0R00V" 0603L 2053.65,995 r90 top value=0
R11 "ERJ-3GEY0R00V" 0603L 1984.06,1215 r90 top value=0
R12 "ERJ-3GEY0R00V" 0603L 1636.11,1215 r90 top value=0
R13 "ERJ-3GEY0R00V" 0603L 1844.88,1215 r90 top value=0
R14 "ERJ-3GEY0R00V" 0603L 1566.52,1215 r90 top value=0
R15 "ERJ-3GEY0R00V" 0603L 1775.29,1215 r90 top value=0
R16 "CRCW06035K10JNEA" 0603L 2220,1115 r180 top value=5.1k
R17 "ERJ-3GEY0R00V" 0603L 1496.93,1215 r90 top value=0
R18 "ERJ-3GEY0R00V" 0603L 1705.7,1215 r90 top value=0
R19 "ERJ-3GEY0R00V" 0603L 1914.47,1215 r90 top value=0
R20 "ERJ-3GEY0R00V" 0603L 1914.47,1483.21 r180 top value=0
R21 "ERJ-3GEY0R00V" 0603L 2053.65,1215 r90 top value=0
R22 "RC0603JR-07820RL" 0603L 1105,1925 r180 top value=820
R23 "RC0603JR-07820RL" 0603L 1105,1765 r180 top value=820
R24 "RG1608P-202-B-T5" 0603L 661,4477.44 r270 top value=2.00k
R25 "RC0603JR-07820RL" 0603L 1105,1600 r180 top value=820
R26 "ERJ-3GEY0R00V" 0603L 1695.51,805 r0 top value=0
R27 "ERJ-3GEY0R00V" 0603L 1516.93,803.25 r180 top value=0
R28 "ERJ-3GEY0R00V" 0603L 1874.75,290 r0 top value=0
R29 "ERJ-3GEY0R00V" 0603L 785,1300 r0 bottom value=0
R30 "ERJ-3GEY0R00V" 0603L 1160,1300 r0 bottom value=0
R31 "ERJ-3GEY0R00V" 0603L 2055.25,805.11 r0 top value=0
R32 "ERJ-3GEY0R00V" 0603L 1135,775 r90 bottom value=0
R33 "ERJ-3GEY0R00V" 0603L 1881.82,805.11 r180 top value=0
R34 "ERJ-3GEY0R00V" 0603L 1435,540 r90 bottom value=0
R35 "ERJ-3GEY0R00V" 0603L 1150,680 r180 top value=0
R36 "ERJ-3GEY0R00V" 0603L 2493.27,345 r0 bottom value=0
R37 "CRCW060310K0JNEA" 0603L 1266.81,347.4 r180 top value=10k
R38 "ERJ-3GEY0R00V" 0603L 2495,405 r0 bottom value=0
R39 "ERJ-3GEY0R00V" 0603L 1375,540 r90 bottom value=0
R40 "CRCW12061R50FKEA" 1206L 2810,4105 r0 top value=1.50
R41 "CRCW12061R50FKEA" 1206L 1810,4100 r0 top value=1.50
R42 "CRCW12061R50FKEA" 1206L 745,4100 r0 top value=1.50
R43 "CRCW060310R0JNEA" 0603L 2505.94,3213.19 r90 top value=10
R44 "CRCW060310R0JNEA" 0603L 1490,3215 r90 top value=10
R45 "CRCW060310R0JNEA" 0603L 425,3232.52 r90 top value=10
R46 "CRCW060310R0JNEA" 0603L 2470,3090 r180 top value=10
R47 "CRCW060310R0JNEA" 0603L 1438.45,3074.13 r180 top value=10
R48 "CRCW060310R0JNEA" 0603L 390.42,3106.39 r180 top value=10
R49 "CRCW060310R0JNEA" 0603L 2955,2780 r90 top value=10
R50 "CRCW060310R0JNEA" 0603L 1935,2780 r90 top value=10
R51 "CRCW060310R0JNEA" 0603L 891.77,2802.05 r90 top value=10
R52 "CRCW060310R0JNEA" 0603L 2875,2780 r90 top value=10
R53 "CRCW060310R0JNEA" 0603L 1845,2780 r90 top value=10
R54 "CRCW060310R0JNEA" 0603L 813.03,2801.12 r90 top value=10
R55 "CRCW12061R50FKEA" 1206L 3285,3295 r90 top value=1.50
R56 "CRCW12061R50FKEA" 1206L 2275,3300.88 r90 top value=1.50
R57 "CRCW12061R50FKEA" 1206L 1205,3220 r90 top value=1.50
R58 "ERJ-3GEY0R00V" 0603L 985,2295 r90 top value=0
R59 "CRCW060356R0JNEA" 0603L 1165,570 r90 top value=56
R60 "CSS2725FT1L00" CSS2725_001 945,2510 r0 top value=0.001
R61 "ERJ-3GEY0R00V" 0603L 902.6,2295 r90 top value=0
R62 "TNPW060310K0BEEA" TNPW0603 2956.85,760 r0 top value=10.0k
R63 "TNPW060310K0BEEA" TNPW0603 2956.85,610 r0 top value=10.0k
R64 "TNPW060310K0BEEA" TNPW0603 2956.85,450 r0 top value=10.0k
R65 "CRCW0603110KFKEA" 0603L 230,1280 r180 bottom value=110k
R66 "CRCW06034K99FKEA" 0603L 255,1175 r90 bottom value=4.99k
R67 "CRCW0603110KFKEA" 0603L 676.39,1175 r90 top value=110k
R68 "CRCW0603110KFKEA" 0603L 676.39,1057.93 r90 top value=110k
R69 "CRCW0603110KFKEA" 0603L 676.39,940.86 r90 top value=110k
R70 "CRCW06034K99FKEA" 0603L 753.08,1175 r270 top value=4.99k
R71 "CRCW06034K99FKEA" 0603L 753.08,1057.93 r270 top value=4.99k
R72 "CRCW06034K99FKEA" 0603L 753.08,940.86 r270 top value=4.99k
R73 "ERA-3ARW103V" 0603L 200,1120 r90 bottom value=10.0k
R74 "ERA-3ARW103V" 0603L 935,264.71 r0 bottom value=10.0k
R75 "ERJ-3GEY0R00V" 0603L 486.85,616.22 r270 bottom value=0
R76 "ERJ-3GEY0R00V" 0603L 1138.27,347.4 r0 top value=0
R77 "ERA-3ARW103V" 0603L 365,616.22 r90 bottom value=10.0k
R78 "RP73PF2A1K0BTDF" 0805L 447.85,1552.3 r0 bottom value=1.00k
R80 "ERJ-3GEY0R00V" 0603L 496.85,388.5 r270 bottom value=0
R81 "ERJ-3GEY0R00V" 0603L 521.14,1470 r0 bottom value=0
R82 "RP73PF2A1K0BTDF" 0805L 447.85,1649.36 r0 bottom value=1.00k
R83 "CRCW0603110KFKEA" 0603L 646.85,1438.24 r90 bottom value=110k
R84 "RP73PF2A1K0BTDF" 0805L 447.85,1742.3 r0 bottom value=1.00k
R85 "ERJ-3GEY0R00V" 0603L 761.85,1406.31 r0 bottom value=0
R86 "CRCW06034K99FKEA" 0603L 521.85,1405.72 r0 bottom value=4.99k
R87 "CRCW0603100KJNEA" 0603L 2356.76,1721.91 r270 top value=100k
R88 "3296W-1-504LF" FP-3296W-1-504LF_PTH_Potentiometer_9MM53_4MM83-MFG 3505,2130 r90 top
R89 "RC0603JR-077K5L" 0603L 2146.85,155 r90 top value=7.5k
R90 "3352T-1-253LF" Bourns_3352T 1616.93,135 r180 top value="25 kohm"
R91 "CRCW060310K0JNEA" 0603L 2019.06,1483.21 r180 top value=10k
R92 "3352T-1-253LF" Bourns_3352T 2388.35,135 r180 top value="25 kohm"
S1 "nSLEEP_SW" SW_B12AP 154.33,645.28 r180 top
S2 "DRVOFF_SW" SW_B12AP 685,155 r270 top
SH-J1 "SNT-100-BK-G" SNT-100-BK-G 680,1925 r180 top value=1x2
SH-J2 "SNT-100-BK-G" SNT-100-BK-G 682,1759.41 r180 top value=1x2
SH-J3 "SNT-100-BK-G" SNT-100-BK-G 941,4380 r180 top value=1x2
SH-J4 "SNT-100-BK-G" SNT-100-BK-G 680,1595 r180 top value=1x2
SH-J5 "SNT-100-BK-G" SNT-100-BK-G 3295,2195 r90 top value=1x2
SH-J6 "SNT-100-BK-G" SNT-100-BK-G 3292.4,1585 r180 top value=1x2
SH-J7 "SNT-100-BK-G" SNT-100-BK-G 3295,1905 r90 top value=1x2
SH-J8 "SNT-100-BK-G" SNT-100-BK-G 1990.84,411.73 r180 top value=1x2
SH-J9 "SNT-100-BK-G" SNT-100-BK-G 2705,1930 r180 top value=1x2
TP1 "DRVOFF" Testpoint_Keystone_Miniature 2445,615 r0 top
TP2 "nSLEEP" Testpoint_Keystone_Miniature 1180,895 r0 top
TP3 "LSS" Testpoint_Keystone_Miniature 1365,2745 r0 top
TP4 "nFAULT" Testpoint_Keystone_Miniature 2280,1215 r0 top
TP5 "GND" Testpoint_Keystone_Miniature 1165,1225 r90 top
TP6 "GND" Testpoint_Keystone_Miniature 2761.44,158.56 r180 top
TP7 "GND" Testpoint_Keystone_Miniature 2883.09,1310 r0 top
TP8 "AVDD" Keystone5000 2666.44,1770 r90 top
TP9 "GND" Testpoint_Keystone_Miniature 395,2075 r180 top
TP10 "GND" Testpoint_Keystone_Miniature 650,2500 r90 top
TP11 "PVDD" Keystone5000 2480,1545 r90 top
TP12 "GVDD" Keystone5000 2296.09,1835 r90 top
TP13 "3V3_MCU" Testpoint_Keystone_Miniature 875,1455 r180 top
TP14 "5V" Testpoint_Keystone_Miniature 1080,1455 r0 top
TP15 "GHA_FET" Testpoint_Keystone_Miniature 2602.4,3057.01 r270 top
TP16 "GHB_FET" Testpoint_Keystone_Miniature 1588.09,3088.66 r90 top
TP17 "GHC_FET" Testpoint_Keystone_Miniature 537.44,3106.39 r270 top
TP18 "GLA_FET" Testpoint_Keystone_Miniature 3095,2769.62 r0 top
TP19 "GLB_FET" Testpoint_Keystone_Miniature 2090,2769.62 r180 top
TP20 "GLC_FET" Testpoint_Keystone_Miniature 1041.38,2804.02 r180 top
TP21 "HALL_PWR" Keystone5000 3100,1735 r90 top
TP22 "GND" Keystone5001 2905,1075 r90 top
TP23 "nSLEEP_SW" Testpoint_Keystone_Miniature 416.85,645 r0 top
TP24 "INHA" Testpoint_Keystone_Miniature 657.85,410 r90 top
TP25 "GND" Harwin_D3082-05 3500,2945 r90 top
TP26 "GND" Harwin_D3082-05 400,2490 r270 top
TP27 "GND" Harwin_D3082-05 2902,4829 r90 top
TP28 "GND" Keystone5001 3495,2480 r90 top
TP29 "GND" Keystone5001 155,970 r90 top
TP30 "EXT_VDSLVL" Keystone5000 1660,385 r90 top
TP31 "EXT_HALL_PWR" Keystone5000 3410,1725 r90 top
TP32 "SP" TP_SM_1MM 1054.88,2195 r90 top
TP33 "SN" TP_SM_1MM 850,2195 r90 top
TP34 "OUTA" Testpoint_Keystone_Compact 2790,4347.89 r0 top
TP35 "OUTA" Testpoint_Keystone_Compact 2154.56,4347.89 r0 top
TP36 "OUTA" Testpoint_Keystone_Compact 1519.12,4347.89 r0 top
U1 "DRV8328ARUYR" RUY0028A-MFG 1835,1640 r180 top
U2 "INA180A1IDBVR" DBV0005A_N 950,2085 r180 top
U3 "TPS7A1633QDGNRQ1" DGN0008B_N 3030,2075 r0 top
U4 "TPD4S009DCKR" DCK0006A_N 536.85,1158.5 r180 bottom
ZZ1 "This Assembly Note is for PCB labels only" AssemblyNoteLabel 4947.75,2616.47 r90 top
ZZ2 "These assemblies are ESD sensitive, ESD precautions shall be observed." AssemblyNote 4770.59,5096.77 r90 top
ZZ3 "These assemblies must be clean and free from flux and all contaminants. Use of no clean flux is not acceptable." AssemblyNote 4593.42,3551.5 r90 top
ZZ4 "These assemblies must comply with workmanship standards IPC-A-610 Class 2, unless otherwise specified." AssemblyNote 4416.26,3876.31 r90 top

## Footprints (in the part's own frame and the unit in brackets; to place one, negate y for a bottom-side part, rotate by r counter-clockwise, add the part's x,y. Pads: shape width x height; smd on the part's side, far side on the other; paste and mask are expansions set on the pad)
0603L [mm] "0603 from SM-752 data"
  rect 0.8x0.85 smd: 1(-0.7,0) 2(0.7,0)
  silkscreen extent -0.07,-0.33 0.07,0.33, body extent -0.87,-0.47 0.87,0.47, height 1
0805L [mm] "0805 from SM-752 data"
  rect 1.1x1.4 smd: 1(-0.75,0) 2(0.75,0)
  body extent -1.1,-0.72 1.1,0.72, height 1.45
1206_190L [mm] "1206_190"
  rect 1.1x1.75 smd: 1(-1.35,0) 2(1.35,0)
  silkscreen extent -0.4,-0.77 0.4,0.77, body extent -1.75,-0.95 1.75,0.95, height 1.9
1206L [mm] "1206 from SM-752 data"
  rect 1.1x1.75 smd: 1(-1.35,0) 2(1.35,0)
  silkscreen extent -0.4,-0.77 0.4,0.77, body extent -1.7,-0.9 1.7,0.9, height 1.35
1210_210L [mm] "1210"
  rect 1.1x2.6 smd: 1(-1.35,0) 2(1.35,0)
  silkscreen extent -0.4,-1.2 0.4,1.2, body extent -1.7,-1.35 1.7,1.35, height 2.1
2220_280L [mm] "Chip Capacitor, Body 5.7x5.0mm, IPC High Density"
  rect 1.4x5.2 smd: 1(-2.5,0) 2(2.5,0)
  silkscreen extent -1.4,-2.5 1.4,2.5, body extent -2.95,-2.6 2.95,2.65, height 2.8
AssemblyNote [mil] "Assembly Note"
AssemblyNoteLabel [mil] "Assembly Note for PCB Labels"
Bourns_3352T [mm] "TH, 3-Leads, Body 9.53x8.89mm, Pitch 2.54mm"
  rect 1.35x1.35 hole 0.85: 1(-2.54,0)
  round 1.35 hole 0.85: 2(0,0) 3(2.54,0)
  silkscreen extent -4.44,-2.6 4.44,7.31, body extent -4.44,-2.21 4.45,7.32, height 3.81
CAPSMT_62_F80 [mm] "6.3 x 7.7mm:  Chemi-Con F80"
  rect 3.5x1.6 smd: 1(-2.7,0) 2(2.7,0)
  silkscreen extent -3.36,-3.4 3.44,3.4, body extent -3.4,-3.4 3.44,3.4, height 8
CE_Mark_5mm [mil] "Minimum text height for CE Mark"
  silkscreen extent -138,-98 138,98
CSS2725_001 [mm] "STACKPOLE ELECTRONICS"
  rect 3.18x6.86 smd: 1(-2.25,0) 2(2.25,0)
  silkscreen extent -4.13,-3.7 4.13,3.7, body extent -3.53,-3.35 3.53,3.35, height 1.34
DBV0005A_N [mm] "SOT23, 5-Leads, Body 2.9x1.6mm, Pitch 0.95mm, Lead Span 2.8mm, IPC Medium Density"
  rrect17% 1x0.6 smd: 1(-1.375,0.95) 2(-1.375,0) 3(-1.375,-0.95) 4(1.375,-0.95) 5(1.375,0.95)
  silkscreen extent -0.25,-1.55 0.25,1.55, body extent -1.42,-1.46 1.42,1.46, height 1.09
DCK0006A_N [mm] "SOT23, 6-Leads, Body 2x1.3mm, Pitch 0.65mm, Lead Span 2.1mm, IPC Medium Density"
  rrect25% 0.85x0.4 smd: 1(-1.125,0.65) 2(-1.125,0) 3(-1.125,-0.65) 4(1.125,-0.65) 5(1.125,0) 6(1.125,0.65)
  silkscreen extent -1.5,-1.09 0.51,1.09, body extent -1.14,-1 1.14,1, height 0.95
DGN0008B_N [mm] "TSOP, 8-Leads, Body 3x3mm, Pitch 0.65mm, Thermal Pad 1.92x1.60mm, IPC Medium Density"
  rrect100% 1.35x0.45 smd: 1(-2.225,0.975) 2(-2.225,0.325) 3(-2.225,-0.325) 4(-2.225,-0.975) 5(2.225,-0.975) 6(2.225,-0.325) 7(2.225,0.325) 8(2.225,0.975)
  rrect5% 1.88x1.98 smd: 9(0,0)
  silkscreen extent -2.7,-1.55 0.95,1.55, body extent -2.46,-1.5 2.46,1.5, height 1.1
FCC_disclaimer [mil]
FCI_68001-403HLF [mm] "Header, 2.54mm, 3x1, TH"
  rect 1.55x1.55 hole 1.02: 1(-2.54,0)
  round 1.55 hole 1.02: 2(0,0) 3(2.54,0)
  silkscreen extent -3.81,-1.21 3.81,1.5, body extent -3.81,-1.21 3.81,1.21, height 8.38
Fiducial10-20 [mm]
  round 1 smd mask+0.5: 1(0,0)
  Top Layer keep-out circle w1.178: c0,0 r0.5
FP-3296W-1-504LF_PTH_Potentiometer_9MM53_4MM83-MFG [mm]
  rrect8% 1.2x1.2 hole 0.7 paste-1000 mask+0: 1(2.54,0.005)
  round 1.2 hole 0.7 paste-1000 mask+0: 2(0,0.005) 3(-2.54,0.005)
  silkscreen extent -4.89,-2.48 5.77,2.48, body extent -4.99,-2.58 4.99,2.58, height 0.25
Harwin_D3082-05 [mm] "Shorting Plug, 10.16mm spacing, TH"
  round 1.8 hole 1.3: 1(-5.08,0) 2(5.08,0)
  silkscreen extent -3.9,-0.53 3.9,0.53, body extent -5.6,-0.52 5.61,0.52, height 6.63
IEC_HotSurface_Small [mil]
  silkscreen extent -107,-93 107,92
Keystone5000 [mil] "For Keystone 500x miniature loop terminals"
  round 80 hole 40: 1(0,0)
  silkscreen extent -52,-52 52,52, body extent -49,-49 49,49, height 182
Keystone5001 [mil] "For Keystone 500x miniature loop terminals"
  round 80 hole 40: 1(0,0)
  silkscreen extent -52,-52 52,52, body extent -49,-49 49,49, height 182
Keystone_1902C [mil] "Hex Standoff, 4-40 threaded, nylon"
  round 1 on Mech4: 0(0,0)
  body extent -145,-126 146,126, height 501
KTT0002A-MFG [mm]
  rrect10% 1.05x3.82 smd paste+0 mask+0: 1(-2.54,-7.755) 3(2.54,-7.755)
  rrect1% 8.55x7.48 smd paste-1000 mask+0: 4(0,2.545)
  silkscreen extent -5.13,-4.62 5.13,4.62, body extent -5.23,-9.76 5.23,6.39, height 0.25
KYB_1250x3500 [mm] "TH, 2-Leads, Dia 12.5mm, Lead Spacing 5mm"
  rect 1.35x1.35 hole 0.85: 1(-2.5,0)
  round 1.35 hole 0.85: 2(2.5,0)
  silkscreen extent -8,-6.5 6.5,6.5, body extent -6.5,-6.5 6.51,6.5, height 36.51
Label_650x200 [mil] "Thermal Transfer Label"
  round 1 on Mech13: 0(0,0)
  silkscreen extent -325,-100 325,100, body extent -325,-100 325,100, height 1
LED_LTST-C170_Red [mm] "LITE-ON"
  rect 1.2x1.2 smd: 1(-1.05,0) 2(1.05,0)
  silkscreen extent -1.6,-0.99 2.3,1.01, body extent -1.05,-0.67 1.05,0.67, height 1.1
LTST-C170KFKT_Orange [mm] "LITE-ON"
  rect 1.2x1.2 smd: 1(-1.05,0) 2(1.05,0)
  silkscreen extent -1.6,-1.01 2.29,0.99, body extent -1.05,-0.67 1.05,0.67, height 1.1
LTST-C170KGKT_Green [mm] "LITE-ON"
  rect 1.2x1.2 smd: 1(-1.05,0) 2(1.05,0)
  silkscreen extent -1.6,-1.01 2.31,0.99, body extent -1.05,-0.67 1.05,0.67, height 1.1
NetTie_0603 [mm] "Net Tie 0603 size"
  rect 0.8x0.95 smd paste-1: 1(-0.9,0) 2(0.9,0)
  Top Layer region: -0.6,0.406 0.6,0.406 0.6,-0.406 -0.6,-0.406
  silkscreen extent -0.1,-0.38 0.1,0.38
"NY PMS 440 0025 PH" [mm] "4-40 nylon screw and mounting hole"
  round 8 hole 3.2: 1(0,0)
  body extent -3.31,-3.3 3.3,3.3, height 2.69
Phoenix_1792892 [mm] "Terminal Block, 5mm, 5x1, R/A, TH"
  rrect50% 1.7x1.7 hole 1.2: 1(-10,0)
  round 1.7 hole 1.2: 2(-5,0) 3(0,0) 4(5,0) 5(10,0)
  silkscreen extent -12.8,-4.95 12.5,5.55, body extent -12.5,-4.95 12.5,5.55, height 13.6
Phoenix_1902547 [mm] "TH, 2-Leads, Body 19.04x16mm, Pitch 9.52mm"
  rect 1.8x1.8 hole 1.3: 1(-4.76,3.1)
  round 1.8 hole 1.3: 2(4.76,3.1)
  silkscreen extent -10,-8 10.09,8, body extent -9.52,-8 10.09,8, height 22
Phoenix_1904150 [mm] "TH, 3-Leads, Body 28.56x16mm, Pitch 9.52mm"
  rect 1.8x1.8 hole 1.3: 1(-9.52,3.1)
  round 1.8 hole 1.3: 2(0,3.1) 3(9.52,3.1)
  silkscreen extent -14.8,-8 14.85,8, body extent -14.28,-8 14.85,8, height 22
RUY0028A-MFG [mm]
  rrect50% 0.6x0.2 smd paste+0 mask+0: 1(-1.9,1.2) 2(-1.9,0.8) 3(-1.9,0.4) 4(-1.9,0) 5(-1.9,-0.4) 6(-1.9,-0.8) 7(-1.9,-1.2) 15(1.9,-1.2) 16(1.9,-0.8) 17(1.9,-0.4) 18(1.9,0) 19(1.9,0.4) 20(1.9,0.8) 21(1.9,1.2)
  rrect50% 0.2x0.6 smd paste+0 mask+0: 8(-1.2,-1.9) 9(-0.8,-1.9) 10(-0.4,-1.9) 11(0,-1.9) 12(0.4,-1.9) 13(0.8,-1.9) 14(1.2,-1.9) 22(1.2,1.9) 23(0.8,1.9) 24(0.4,1.9) 25(0,1.9) 26(-0.4,1.9) 27(-0.8,1.9) 28(-1.2,1.9)
  rrect5% 2.6x2.6 smd paste-1000 mask+0: 29(0,0)
  silkscreen extent -2.88,-2.05 2.05,2.05, body extent -2.3,-2.3 2.3,2.3, height 0.25
Samtec_SSQ-110-03-x-D [mm] "Receptacle, 2.54mm, 10x2, TH"
  rect 1.55x1.55 hole 1.02: 1(-11.43,1.27)
  round 1.55 hole 1.02: 2(-11.43,-1.27) 3(-8.89,1.27) 4(-8.89,-1.27) 5(-6.35,1.27) 6(-6.35,-1.27) 7(-3.81,1.27) 8(-3.81,-1.27) 9(-1.27,1.27) 10(-1.27,-1.27) 11(1.27,1.27) 12(1.27,-1.27) 13(3.81,1.27) 14(3.81,-1.27) 15(6.35,1.27) 16(6.35,-1.27) 17(8.89,1.27) 18(8.89,-1.27) 19(11.43,1.27) 20(11.43,-1.27)
  silkscreen extent -12.95,-2.48 12.95,3, body extent -12.95,-2.48 12.95,2.48, height 8.51
SNT-100-BK-G [mil] "Samtec STEP model"
  round 1 on Mech3: 0(0,0)
  body extent -100,-50 100,50, height 344
SOD-323 [mm] "NXP recommended land pattern"
  rect 0.6x0.6 smd paste-0.05: 1(-1.1,0) 2(1.1,0)
  silkscreen extent -2.14,-0.86 1.53,0.87, body extent -1.3,-0.67 1.3,0.68, height 1.1
SW_B12AP [mm] "NKK Switches"
  rect 1.35x1.35 hole 0.85 paste+0: 1(-1,2.54)
  round 1.35 hole 0.85 paste+0: 2(-1,0) 3(-1,-2.54)
  silkscreen extent -4.27,-4.4 3.4,4.4, body extent -3.4,-4.39 3.4,4.39, height 22.87
Testpoint_Keystone_Compact [mil] "Compact SMT test point"
  rect 185x135 smd: 1(0,0)
  silkscreen extent -110,-80 110,80, body extent -75,-56 75,56, height 91
Testpoint_Keystone_Miniature [mil] "Miniature SMT test point"
  rect 135x70 smd: 1(0,0)
  silkscreen extent -78,-46 78,45, body extent -52,-20 52,20, height 61
TI_Stacked_Overlay_Small [mil]
  silkscreen extent -418,-98 418,98
TNPW0603 [mm] "Vishay"
  rect 0.5x0.9 smd: 1(-0.75,0) 2(0.75,0)
  silkscreen extent -0.2,-0.6 0.2,0.6, body extent -0.85,-0.47 0.85,0.47, height 0.55
TP_SM_1MM [mm] "1mm Test Point, SMT"
  round 1 smd paste-0.5: 1(0,0)
TSW-102-07-G-S [mm] "Samtec 100mil, 1x2, 230 mil above insulator"
  rrect50% 1.65x1.65 hole 1.016: 1(-1.27,0)
  round 1.65 hole 1.016: 2(1.27,0)
  silkscreen extent -2.54,-1.27 2.54,2.12, body extent -2.54,-1.27 2.54,1.27, height 8.38
TSW-114-07-G-S [mm] "Samtec 100mil, 1x14, 230 mil above insulator"
  rrect6% 1.65x1.65 hole 1.016: 1(-16.51,0)
  round 1.65 hole 1.016: 2(-13.97,0) 3(-11.43,0) 4(-8.89,0) 5(-6.35,0) 6(-3.81,0) 7(-1.27,0) 8(1.27,0) 9(3.81,0) 10(6.35,0) 11(8.89,0) 12(11.43,0) 13(13.97,0) 14(16.51,0)
  silkscreen extent -17.78,-1.27 17.78,1.65, body extent -17.78,-1.27 17.78,1.27, height 8.38
WEEE_Minimum [mil] "WEEElie bin"
  silkscreen extent -95,-172 99,104

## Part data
C1 C49: library part CMP-0086190-1, "CAP, CERM, 1 µF, 6.3 V,+/- 10%, X7R, AEC-Q200 Grade 1, 0603", Cap_Case=0603, Manufacturer=Kemet, TempCo=X7R, Tolerance_%=10%, Value2=6.3V, ValueDisplayed=1µF
C2: library part CMP-0085846-1, "CAP, CERM, 0.1 µF, 6.3 V,+/- 10%, X5R, 0603", Cap_Case=0603, Manufacturer=Kemet, TempCo=X5R, Tolerance_%=10%, Value2=6.3V, ValueDisplayed=0.1µF
C3 C8 C9: library part CMP-0007011-4, "CAP, CERM, 1 uF, 50 V, +/- 10%, X5R, 0603", Cap_Case=0603, Manufacturer=TDK, Supplier Part Number 1=445-7468-1-ND, TempCo=X5R, Tolerance_%=10%, Value1="0.005522 ohm", Value2=50V, ValueDisplayed=1uF
C4 C33: library part CMP-0009304-2, "CAP, CERM, 10 uF, 100 V, +/- 20%, X7R, 2220", Cap_Case=2220, Manufacturer=AVX, Supplier Part Number 1=478-9622-1-ND, TempCo=X7R, Tolerance_%=20%, Value1=Unknown, Value2=100V, ValueDisplayed=10uF
C5 C34: library part CMP-0007470-5, "CAP, CERM, 0.1 uF, 100 V, +/- 10%, X7R, 0603", Cap_Case=0603, Manufacturer=MuRata, Supplier Part Number 1=490-6439-1-ND, TempCo=X7R, Tolerance_%=10%, Value1=Unknown, Value2=100V, ValueDisplayed=0.1uF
